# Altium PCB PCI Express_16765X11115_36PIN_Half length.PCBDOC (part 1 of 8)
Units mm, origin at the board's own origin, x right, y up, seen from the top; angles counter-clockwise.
Board outline 178 x 110.97 mm, 10 copper layers (Top Layer, Int1 (GND), Int2 (Sign), Int3 (Sign), Int4 (PWR), Int5 (GND), Int6 (Sign), Int7 (Sign), Int8 (GND), Bottom Layer), stack 1.429 mm thick; 528 components, 525 nets, 2272 pads, 1491 vias.
Unrouted connection lines stored in the file: 373.
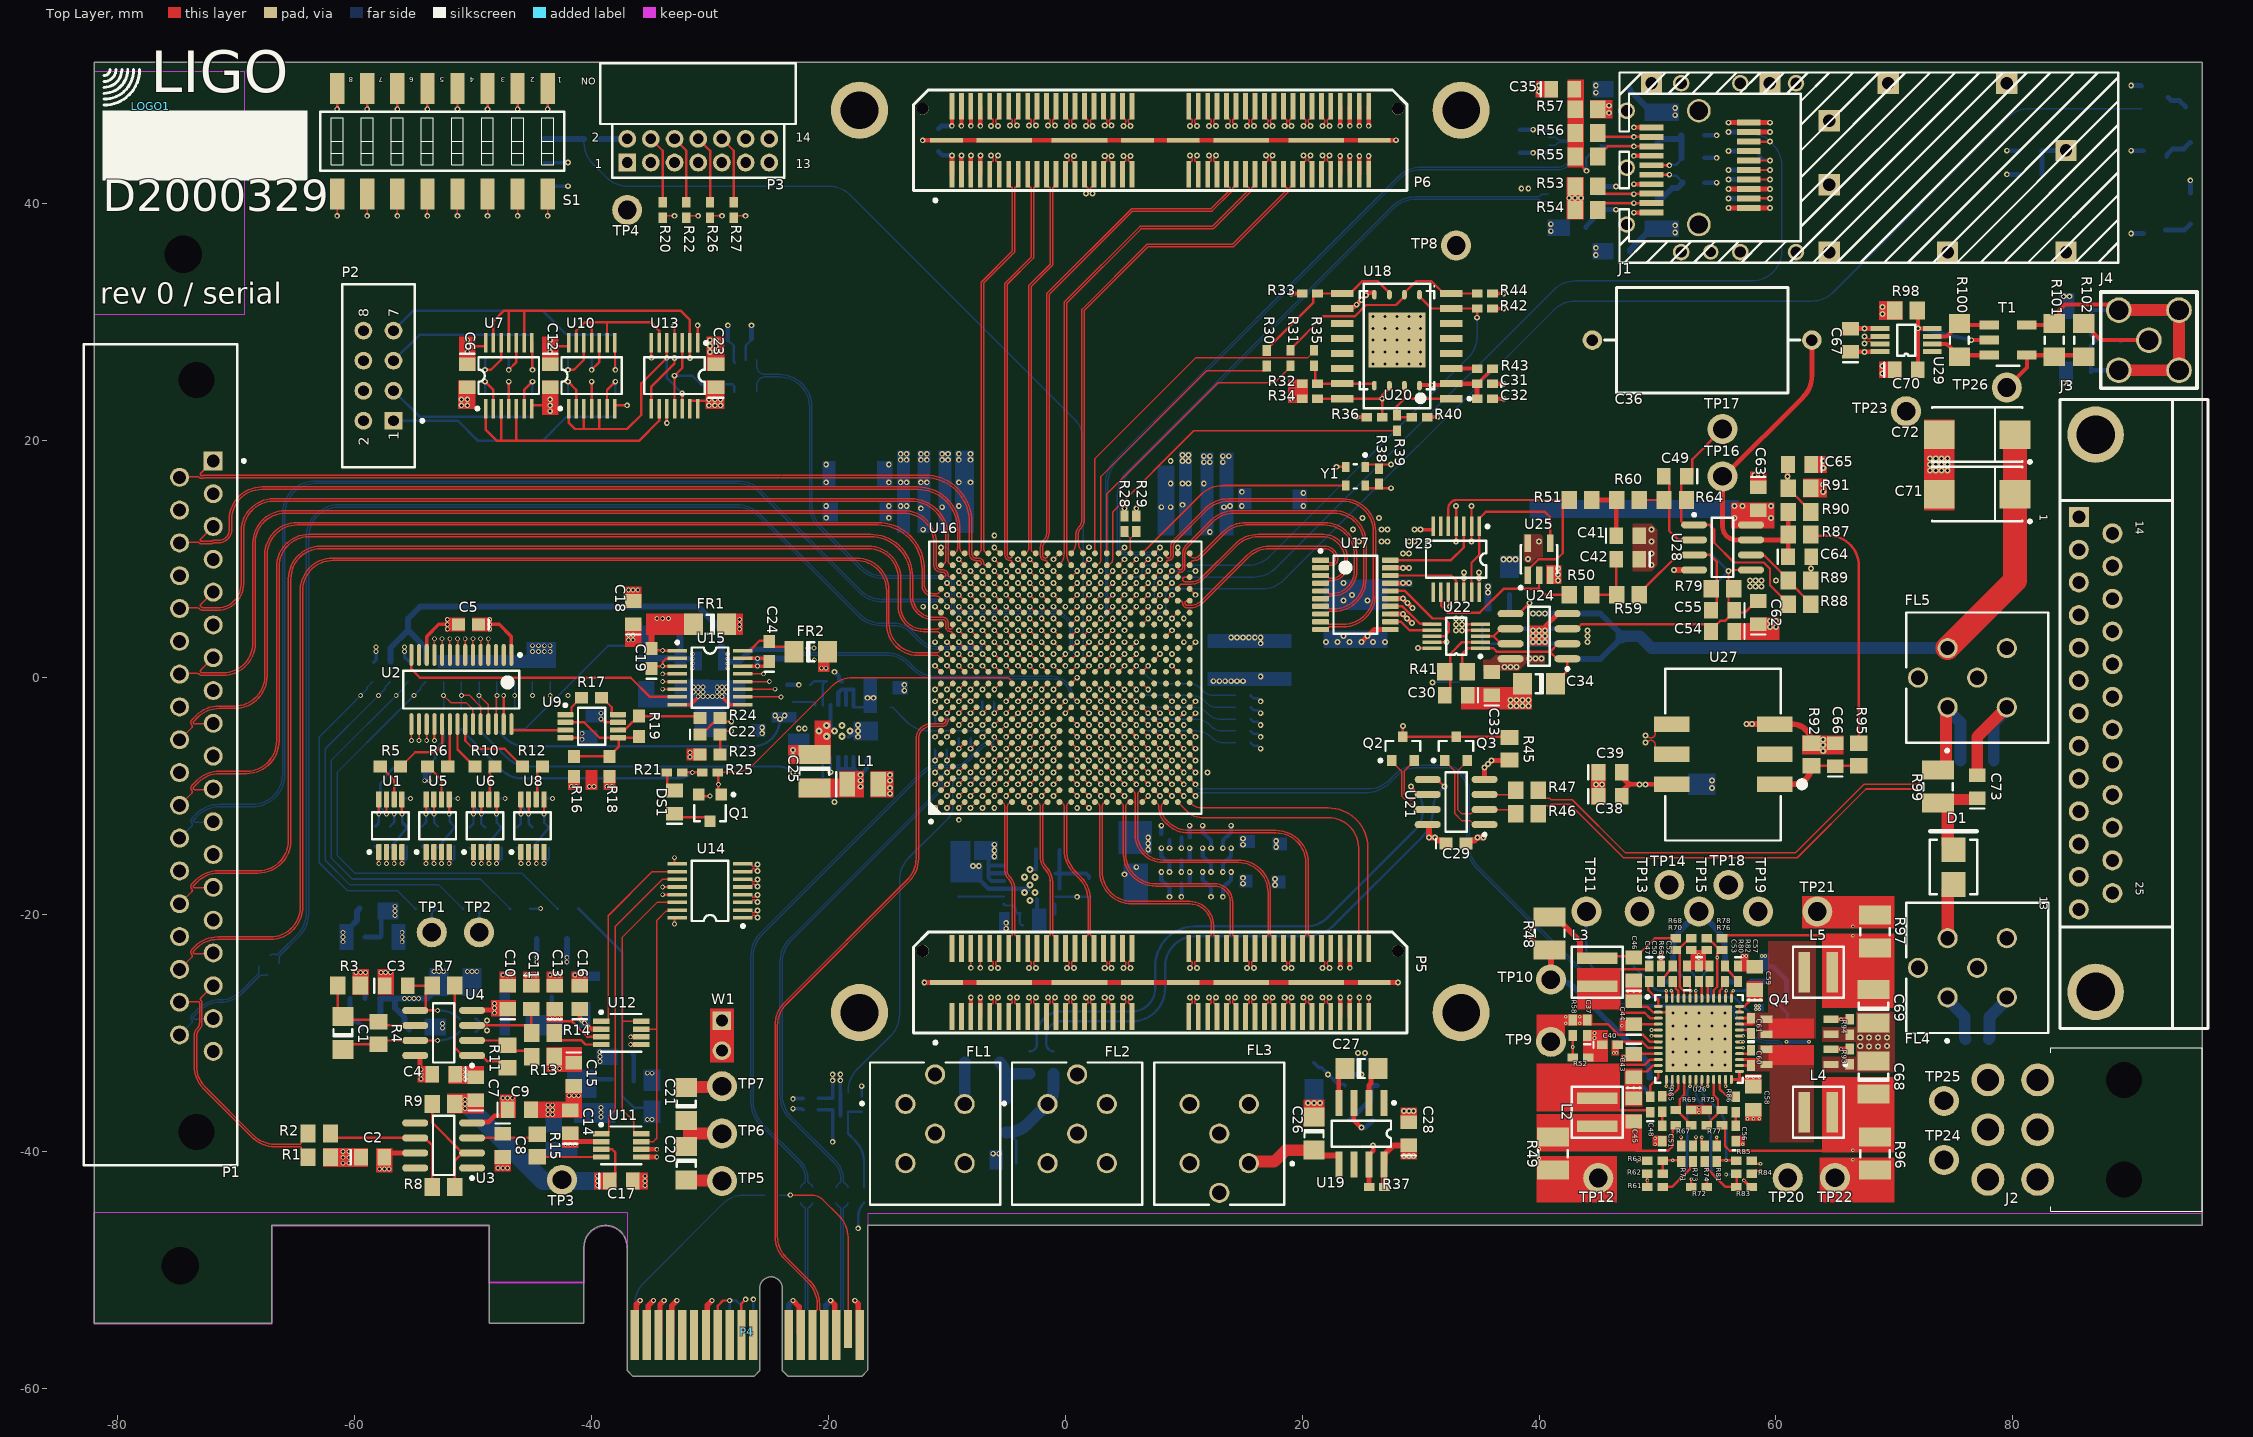
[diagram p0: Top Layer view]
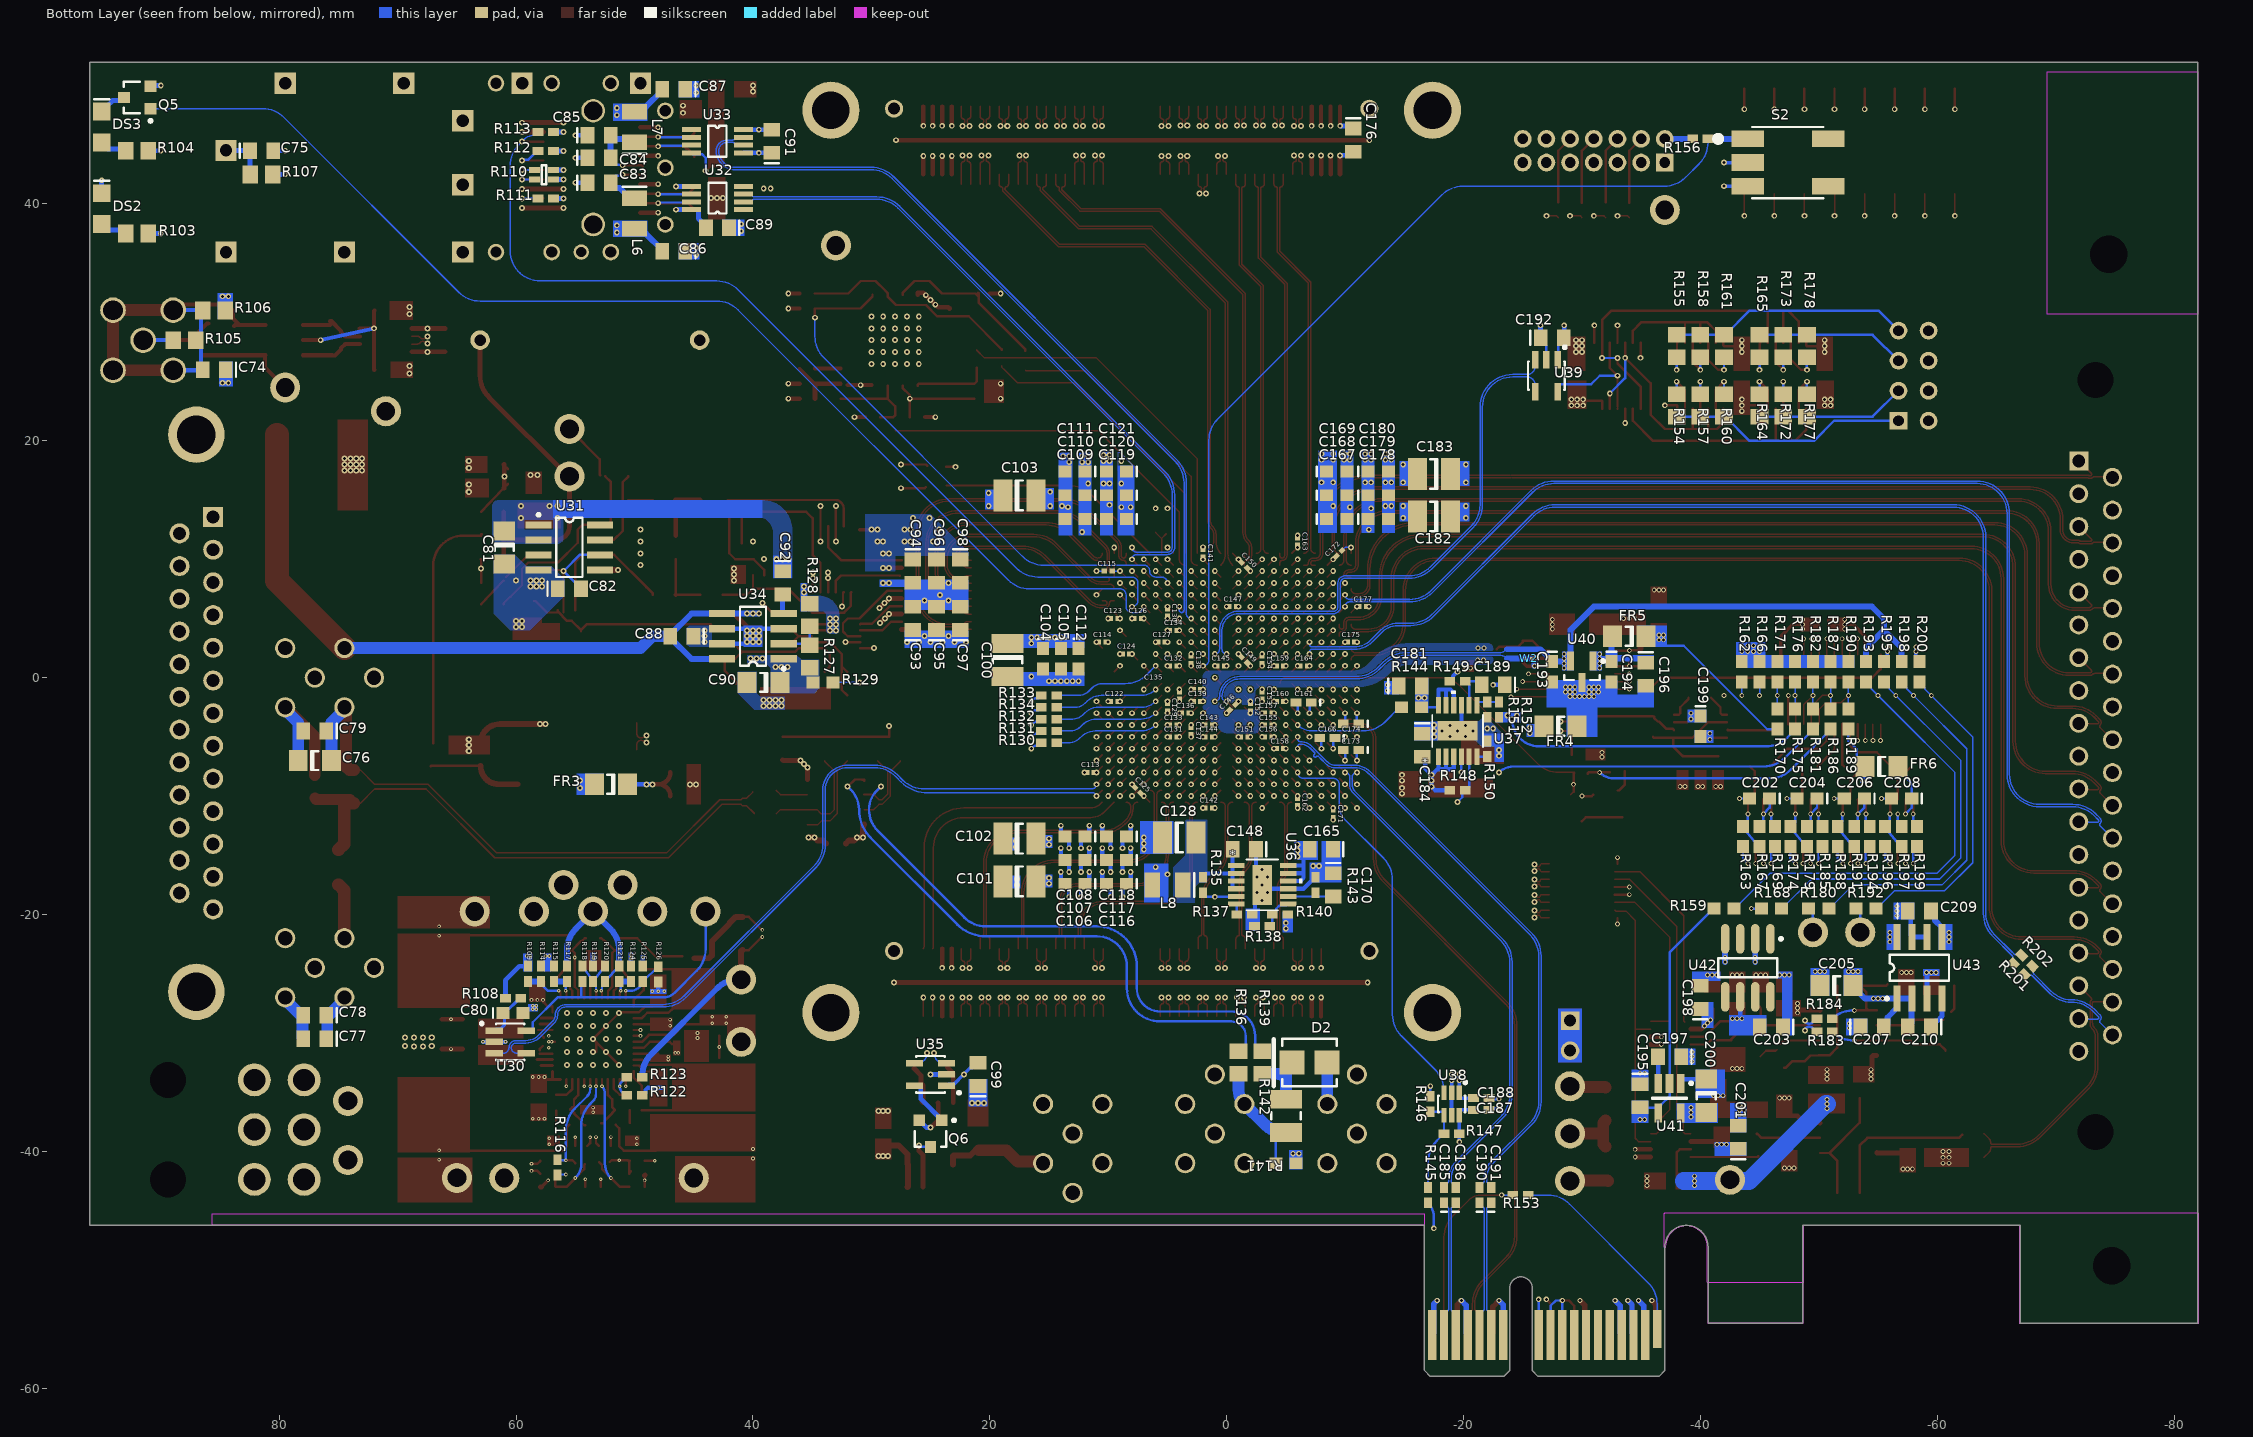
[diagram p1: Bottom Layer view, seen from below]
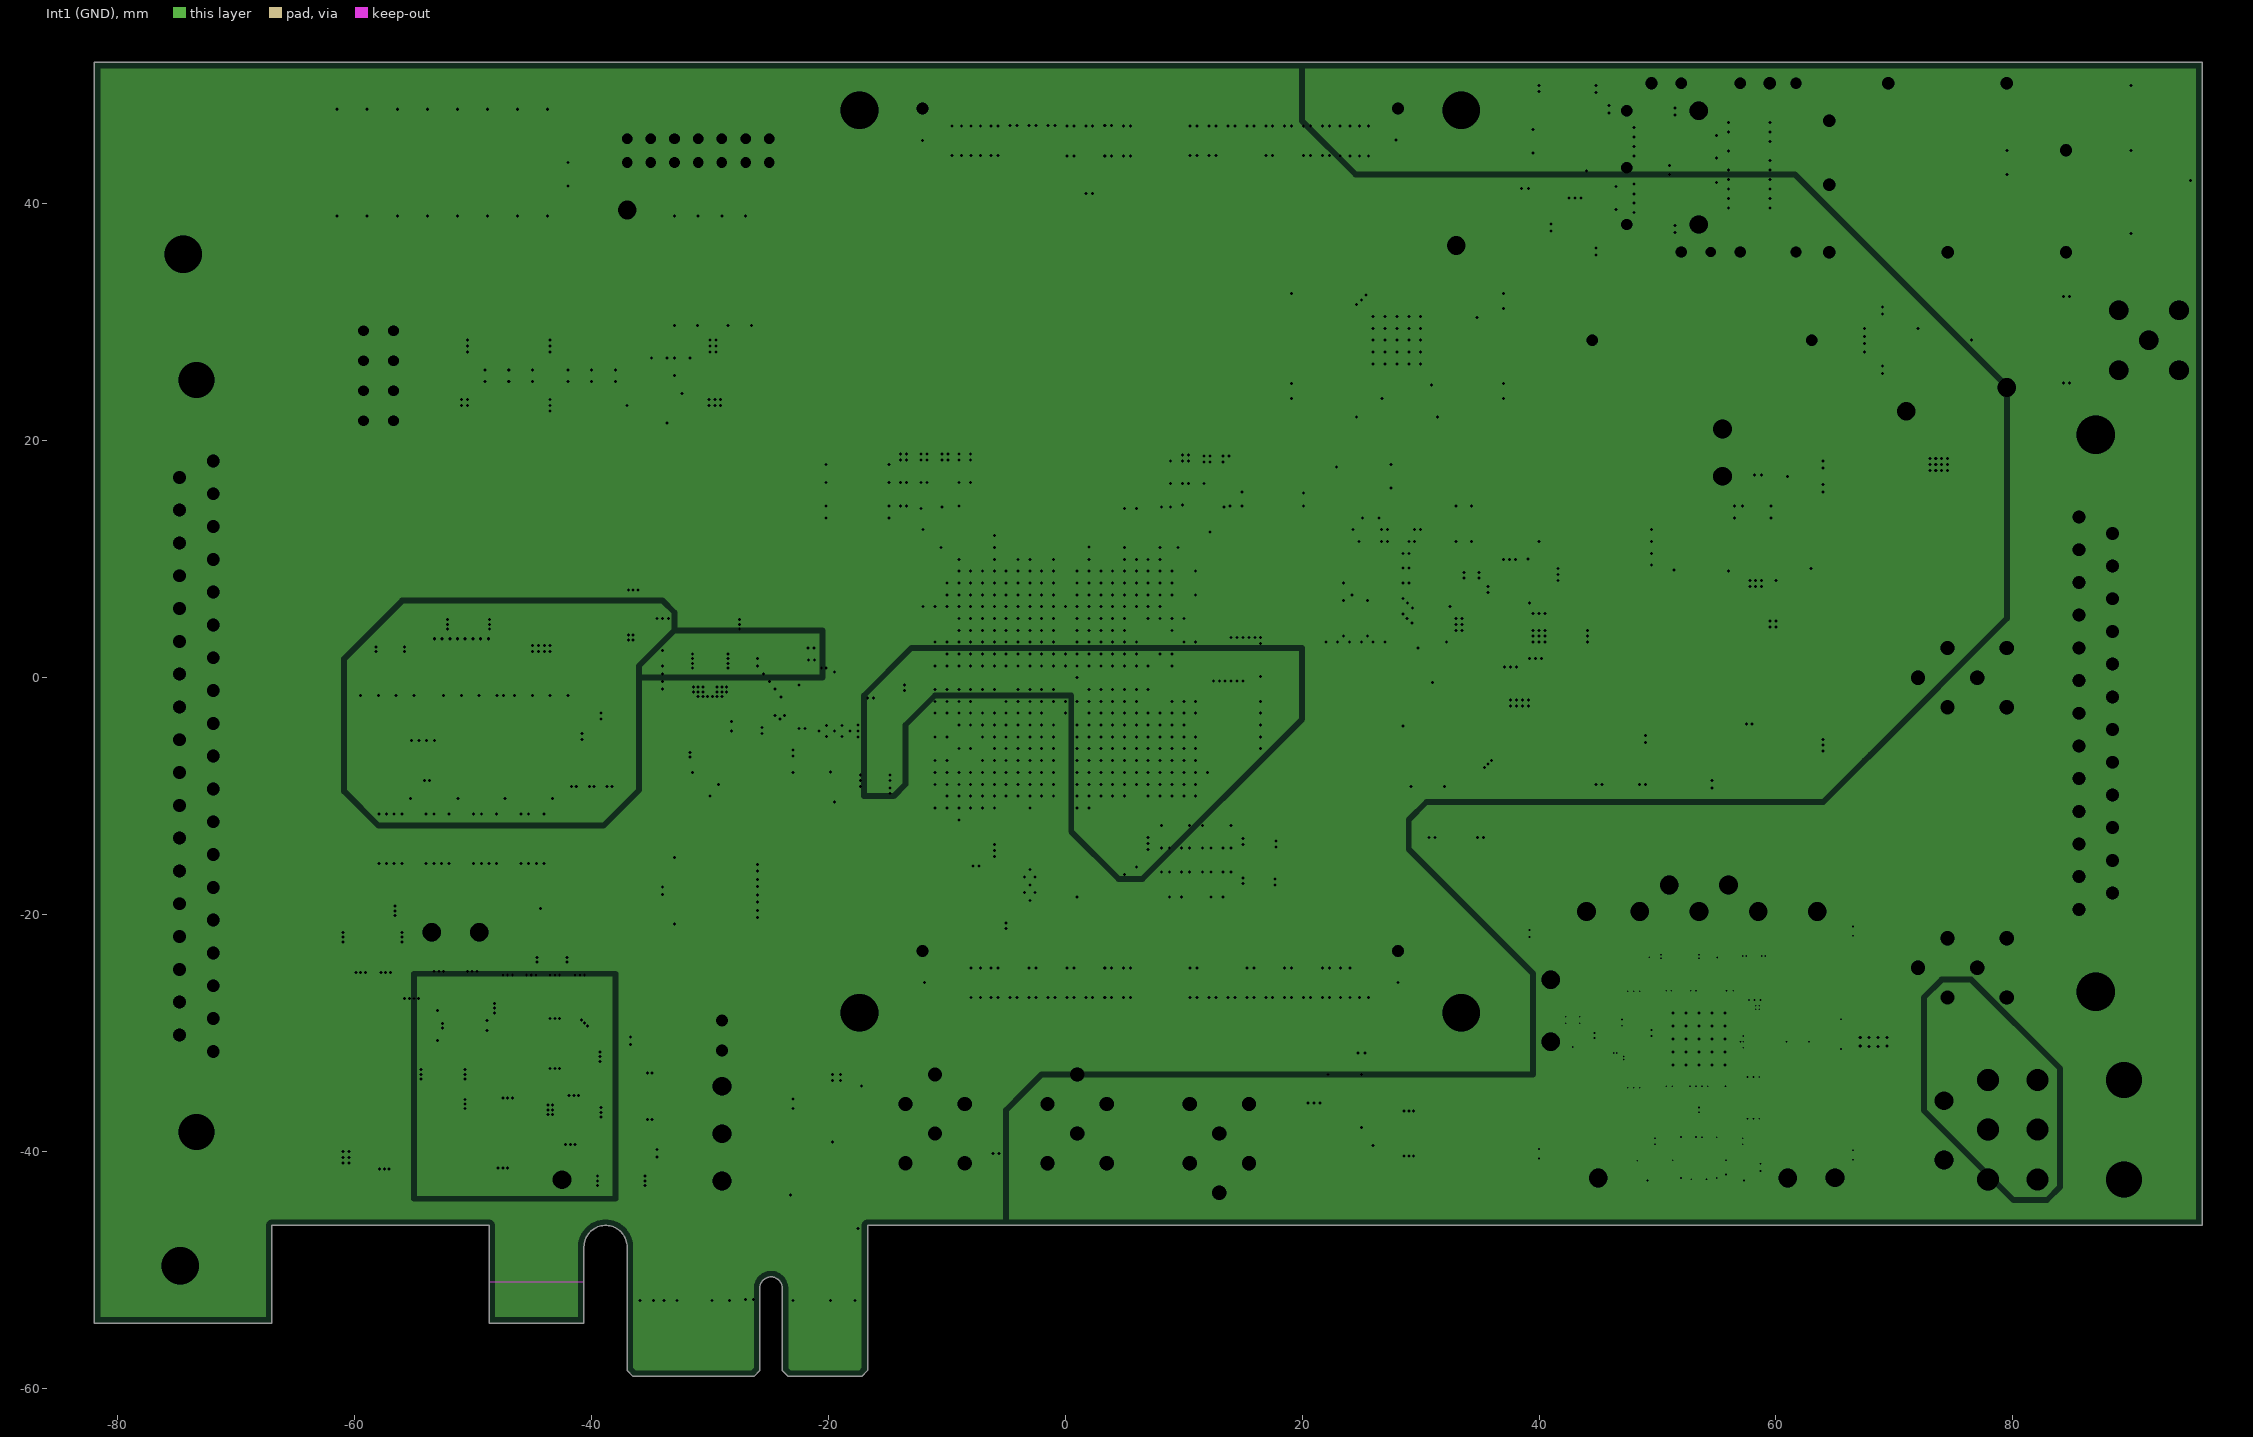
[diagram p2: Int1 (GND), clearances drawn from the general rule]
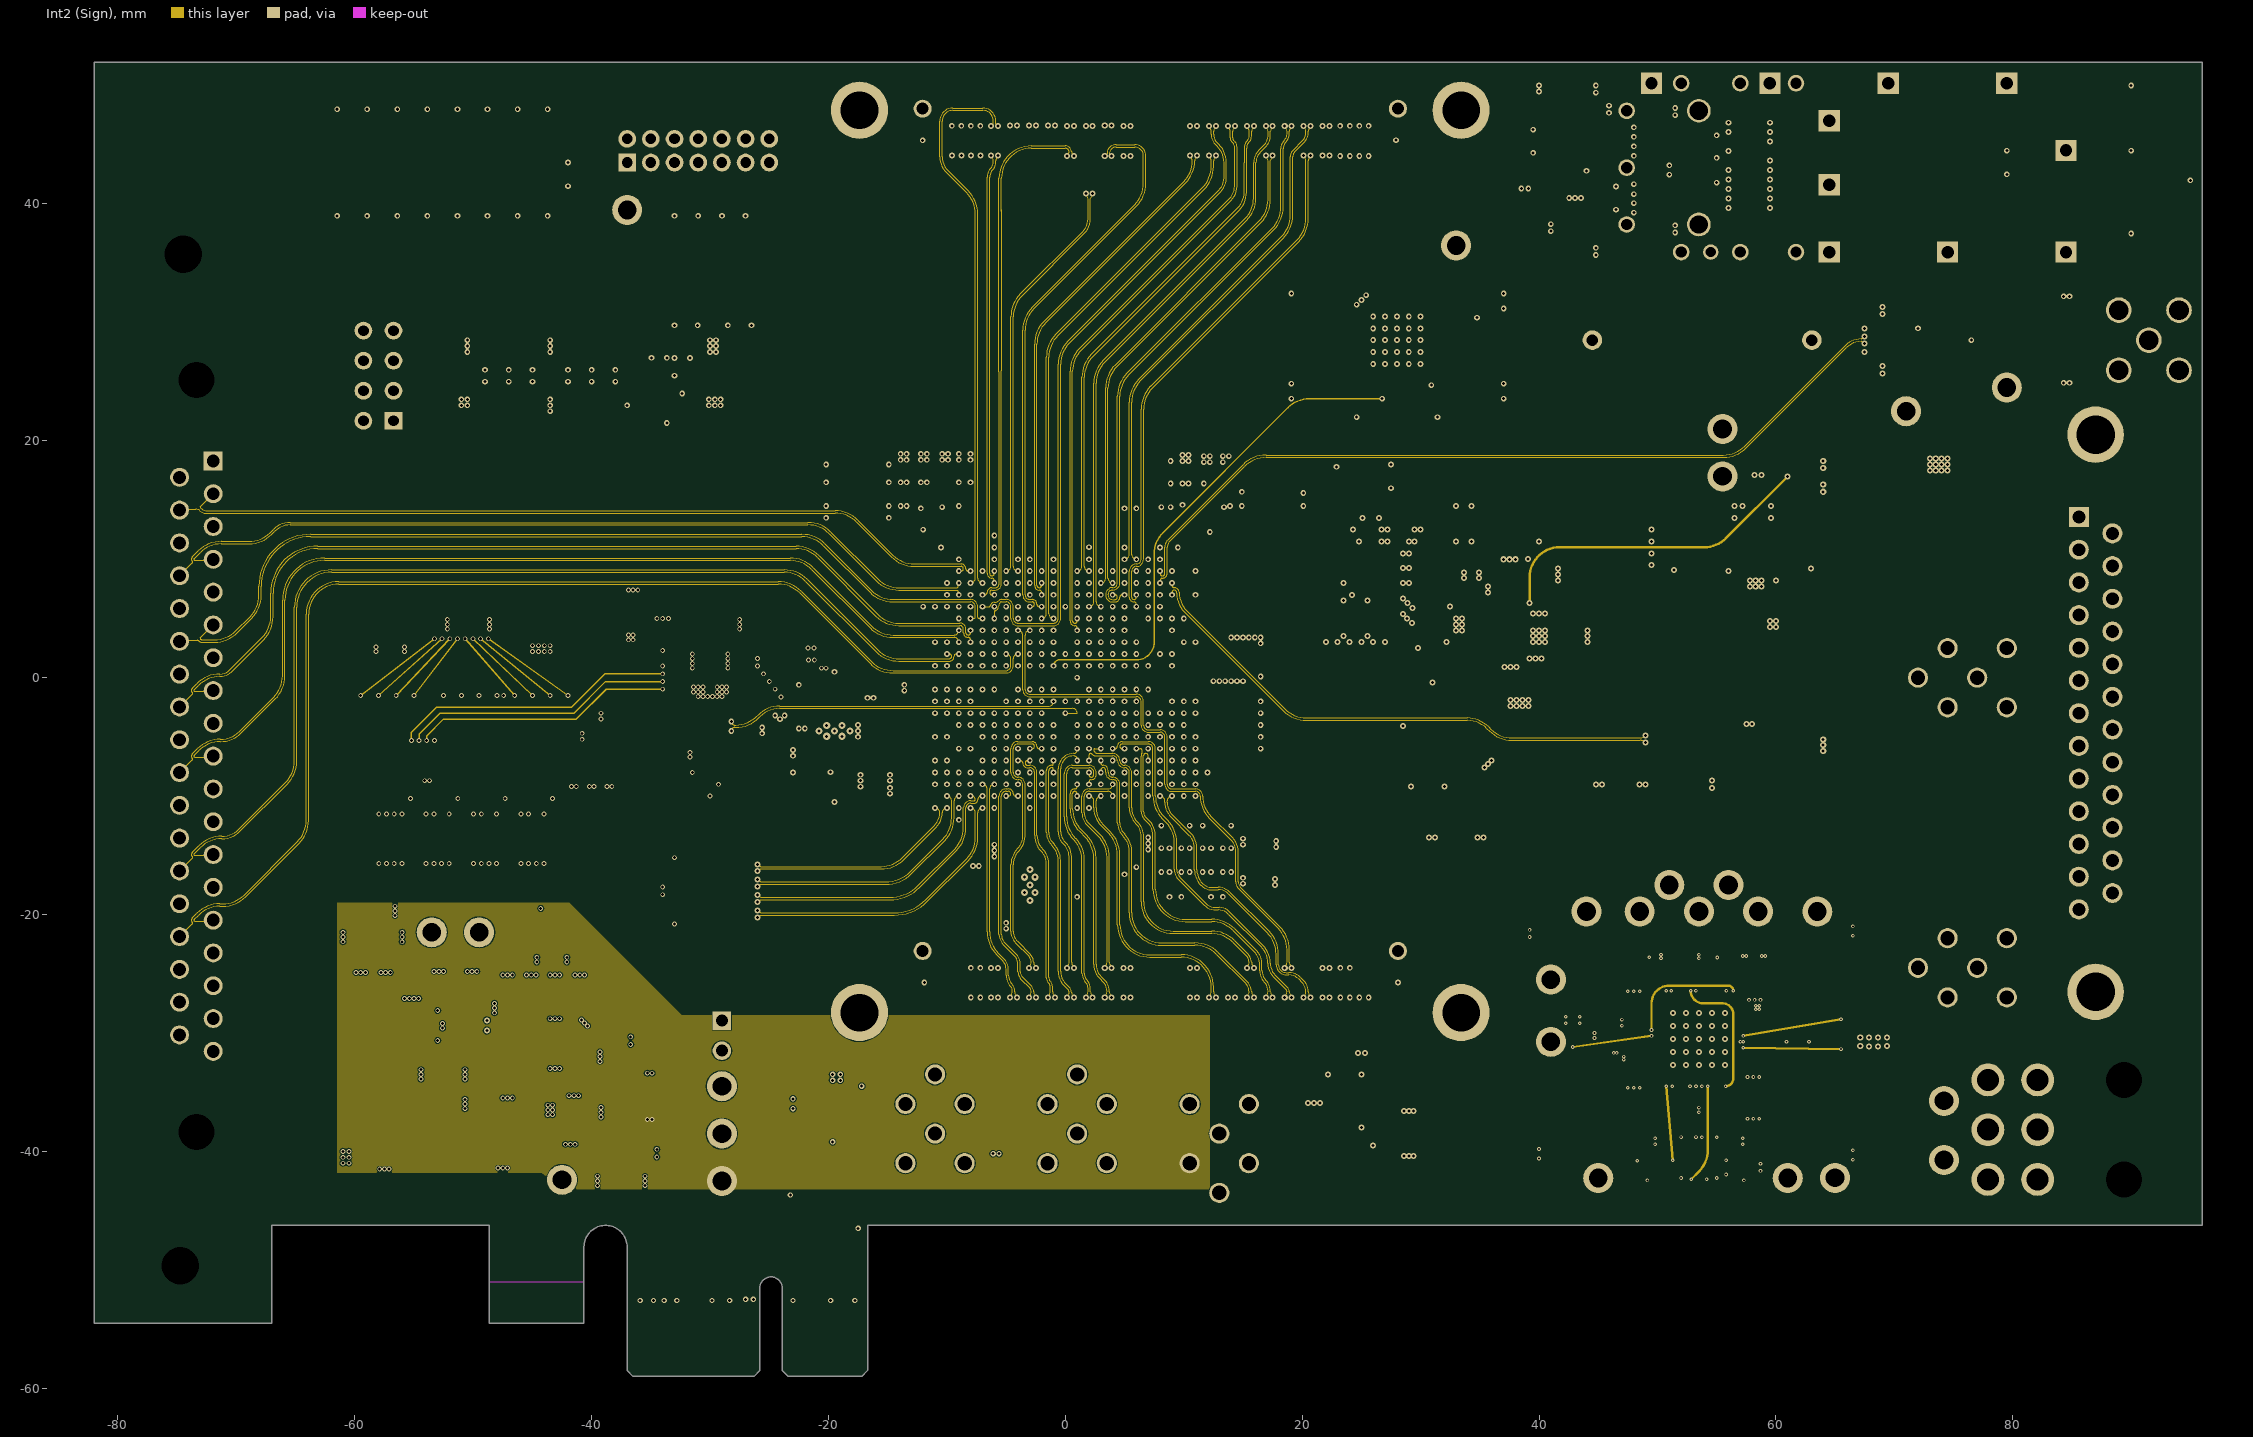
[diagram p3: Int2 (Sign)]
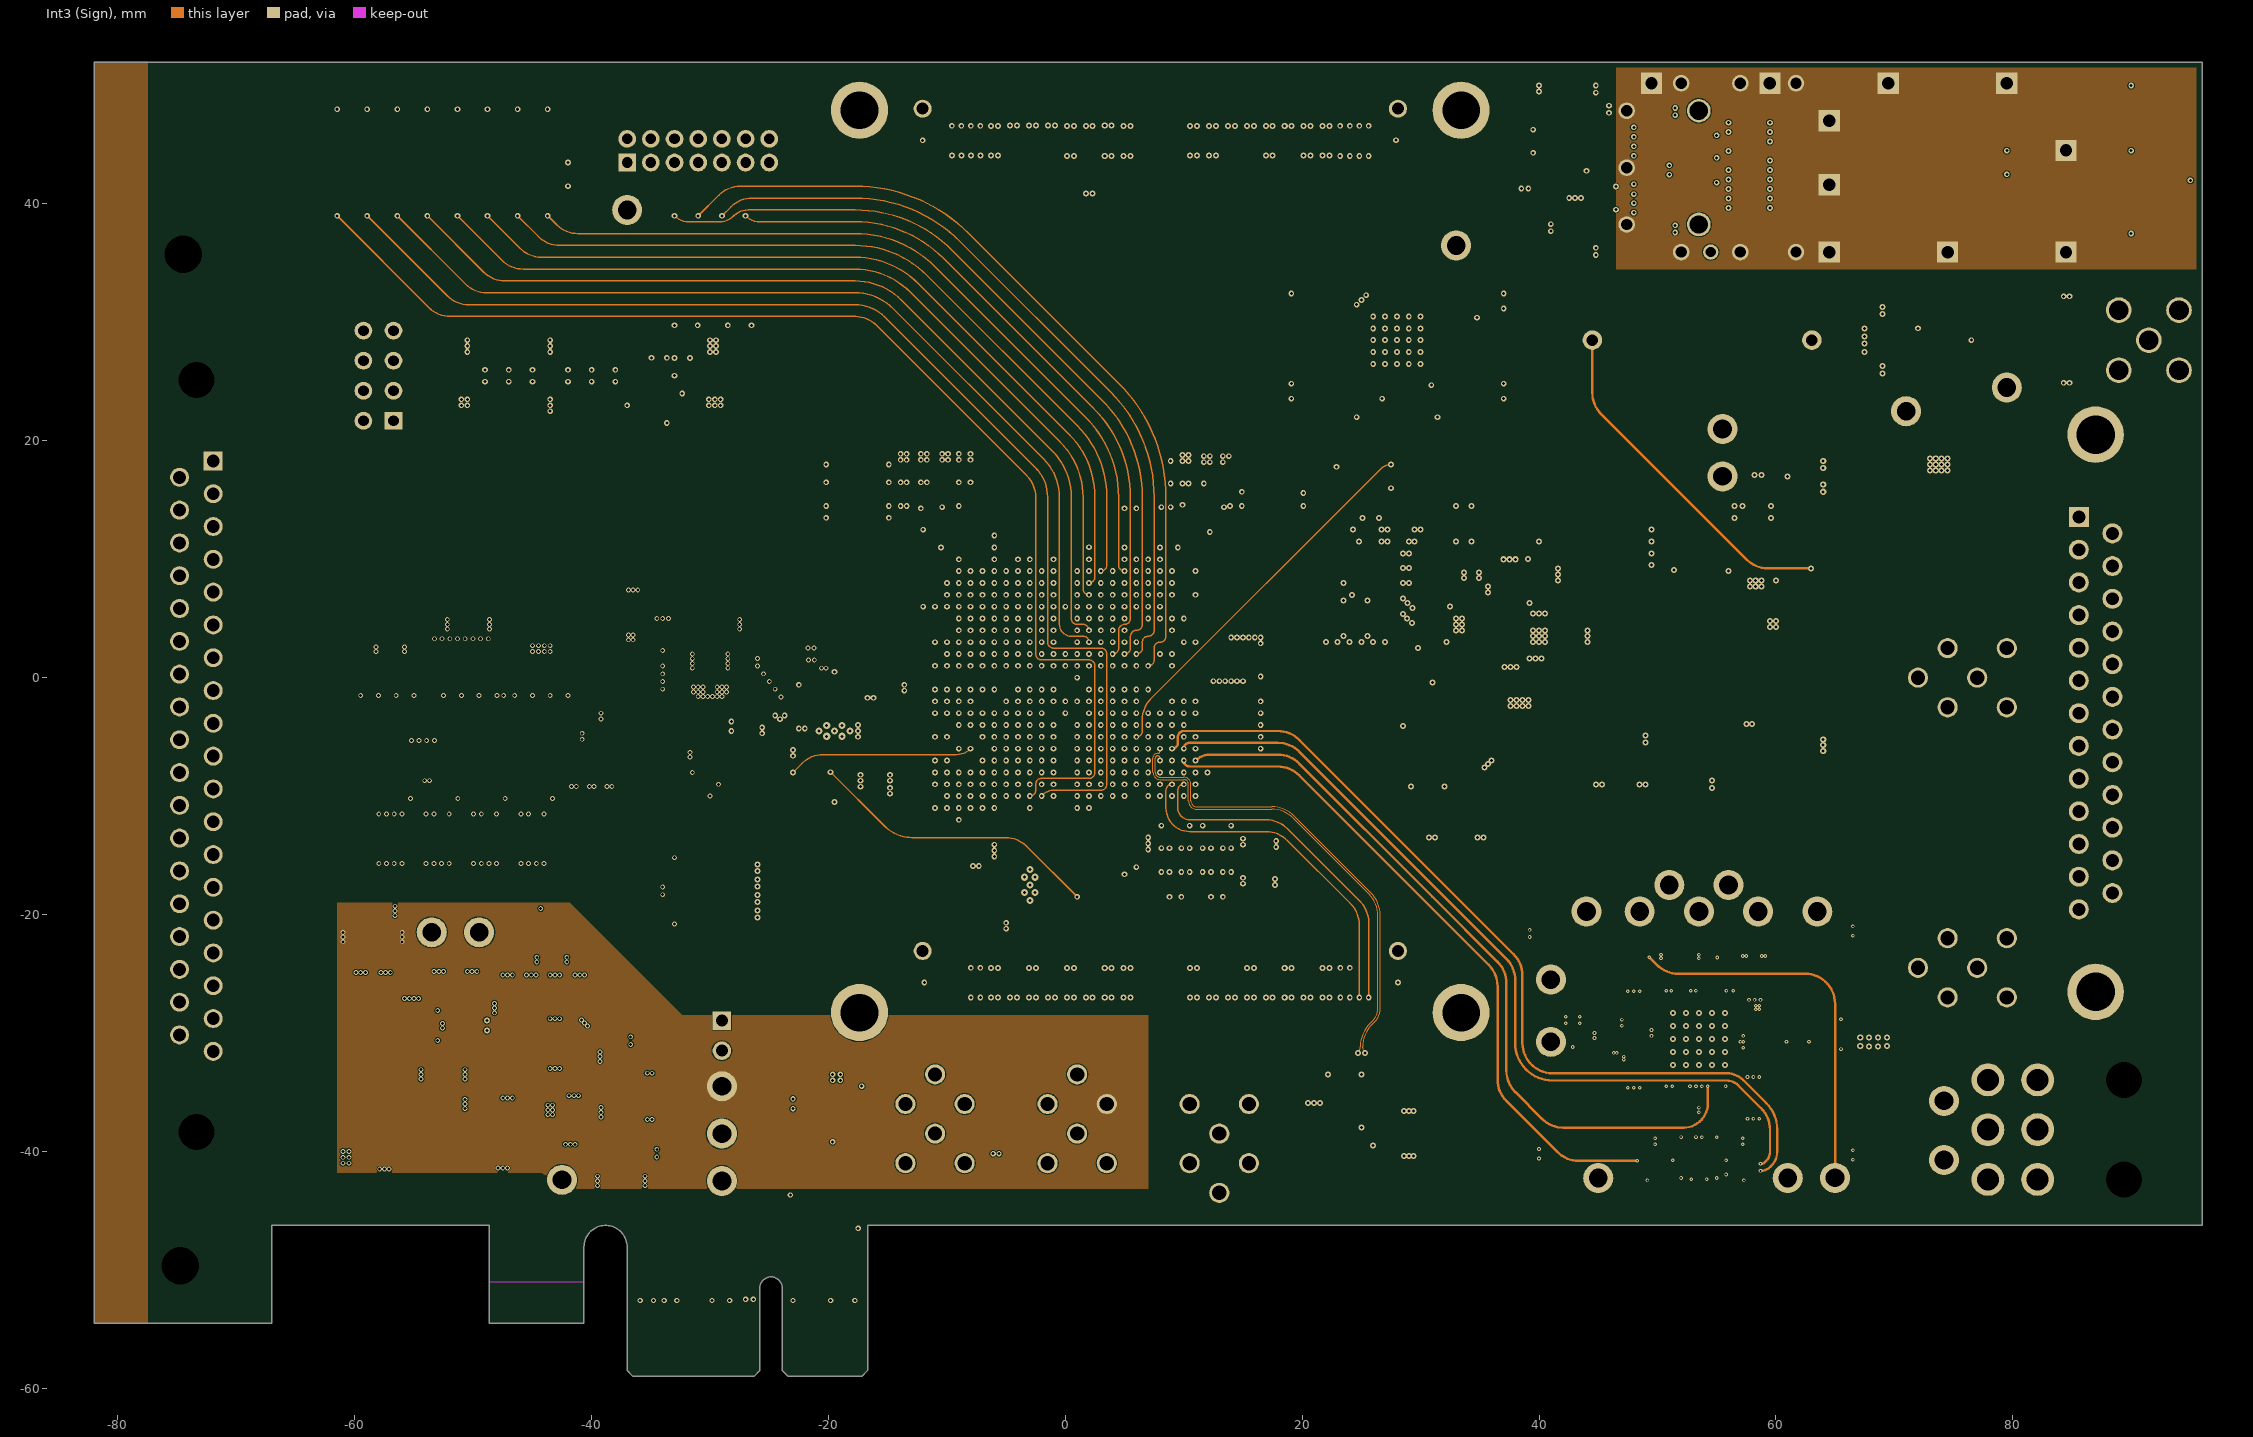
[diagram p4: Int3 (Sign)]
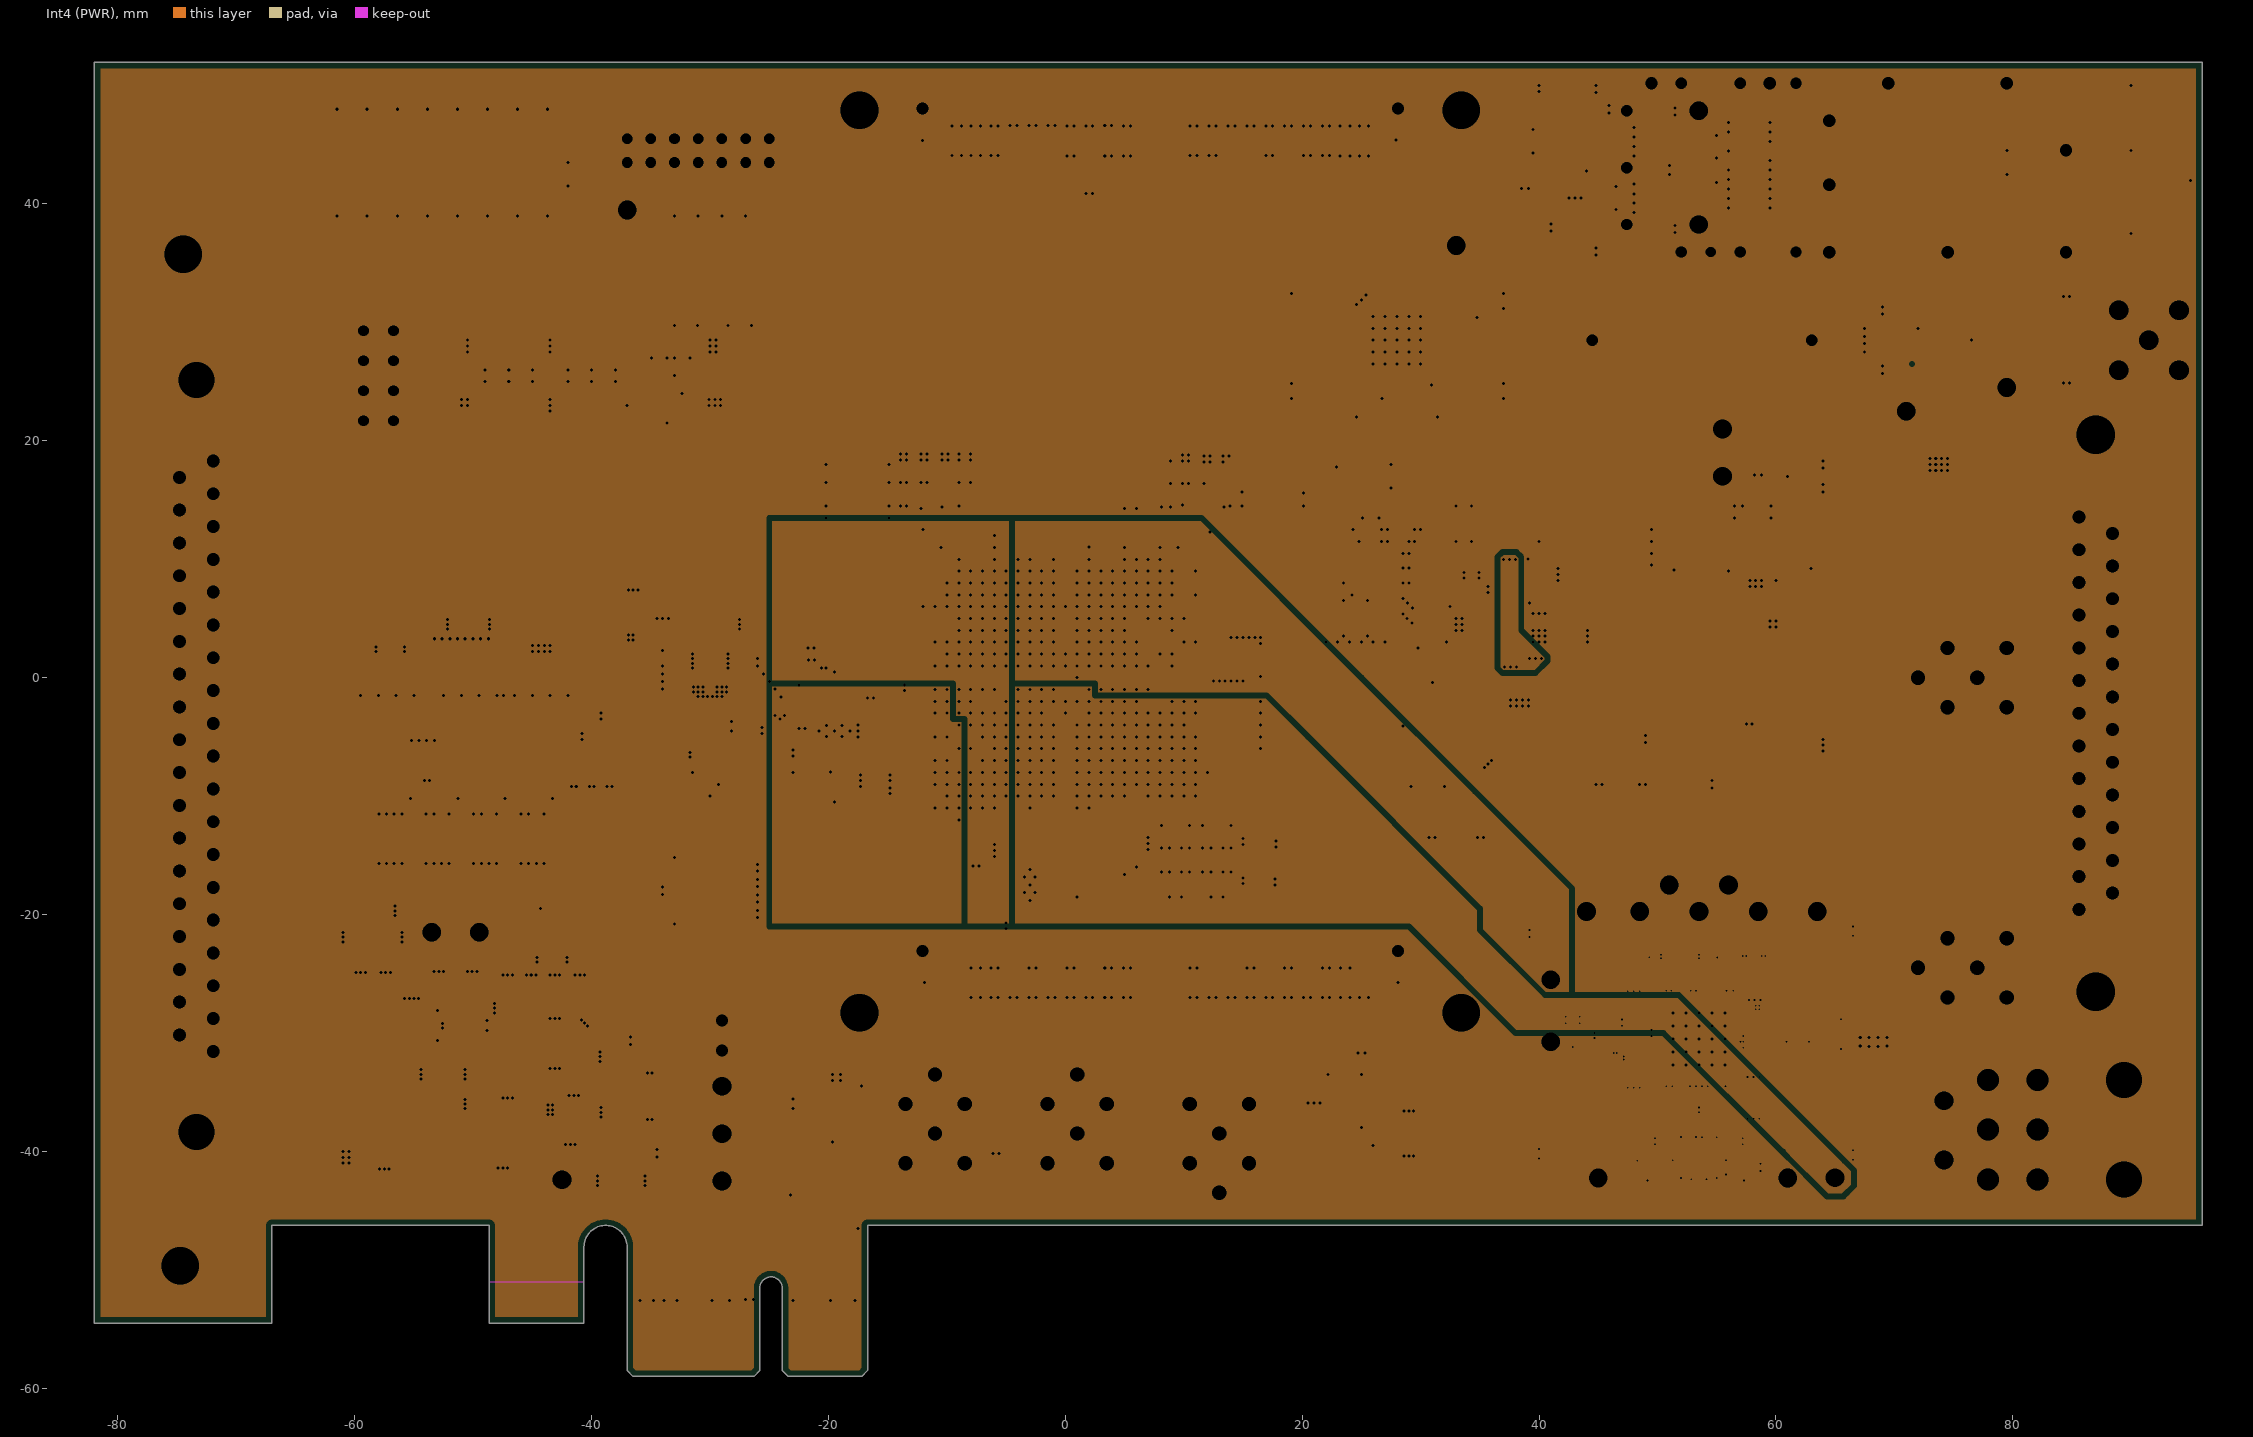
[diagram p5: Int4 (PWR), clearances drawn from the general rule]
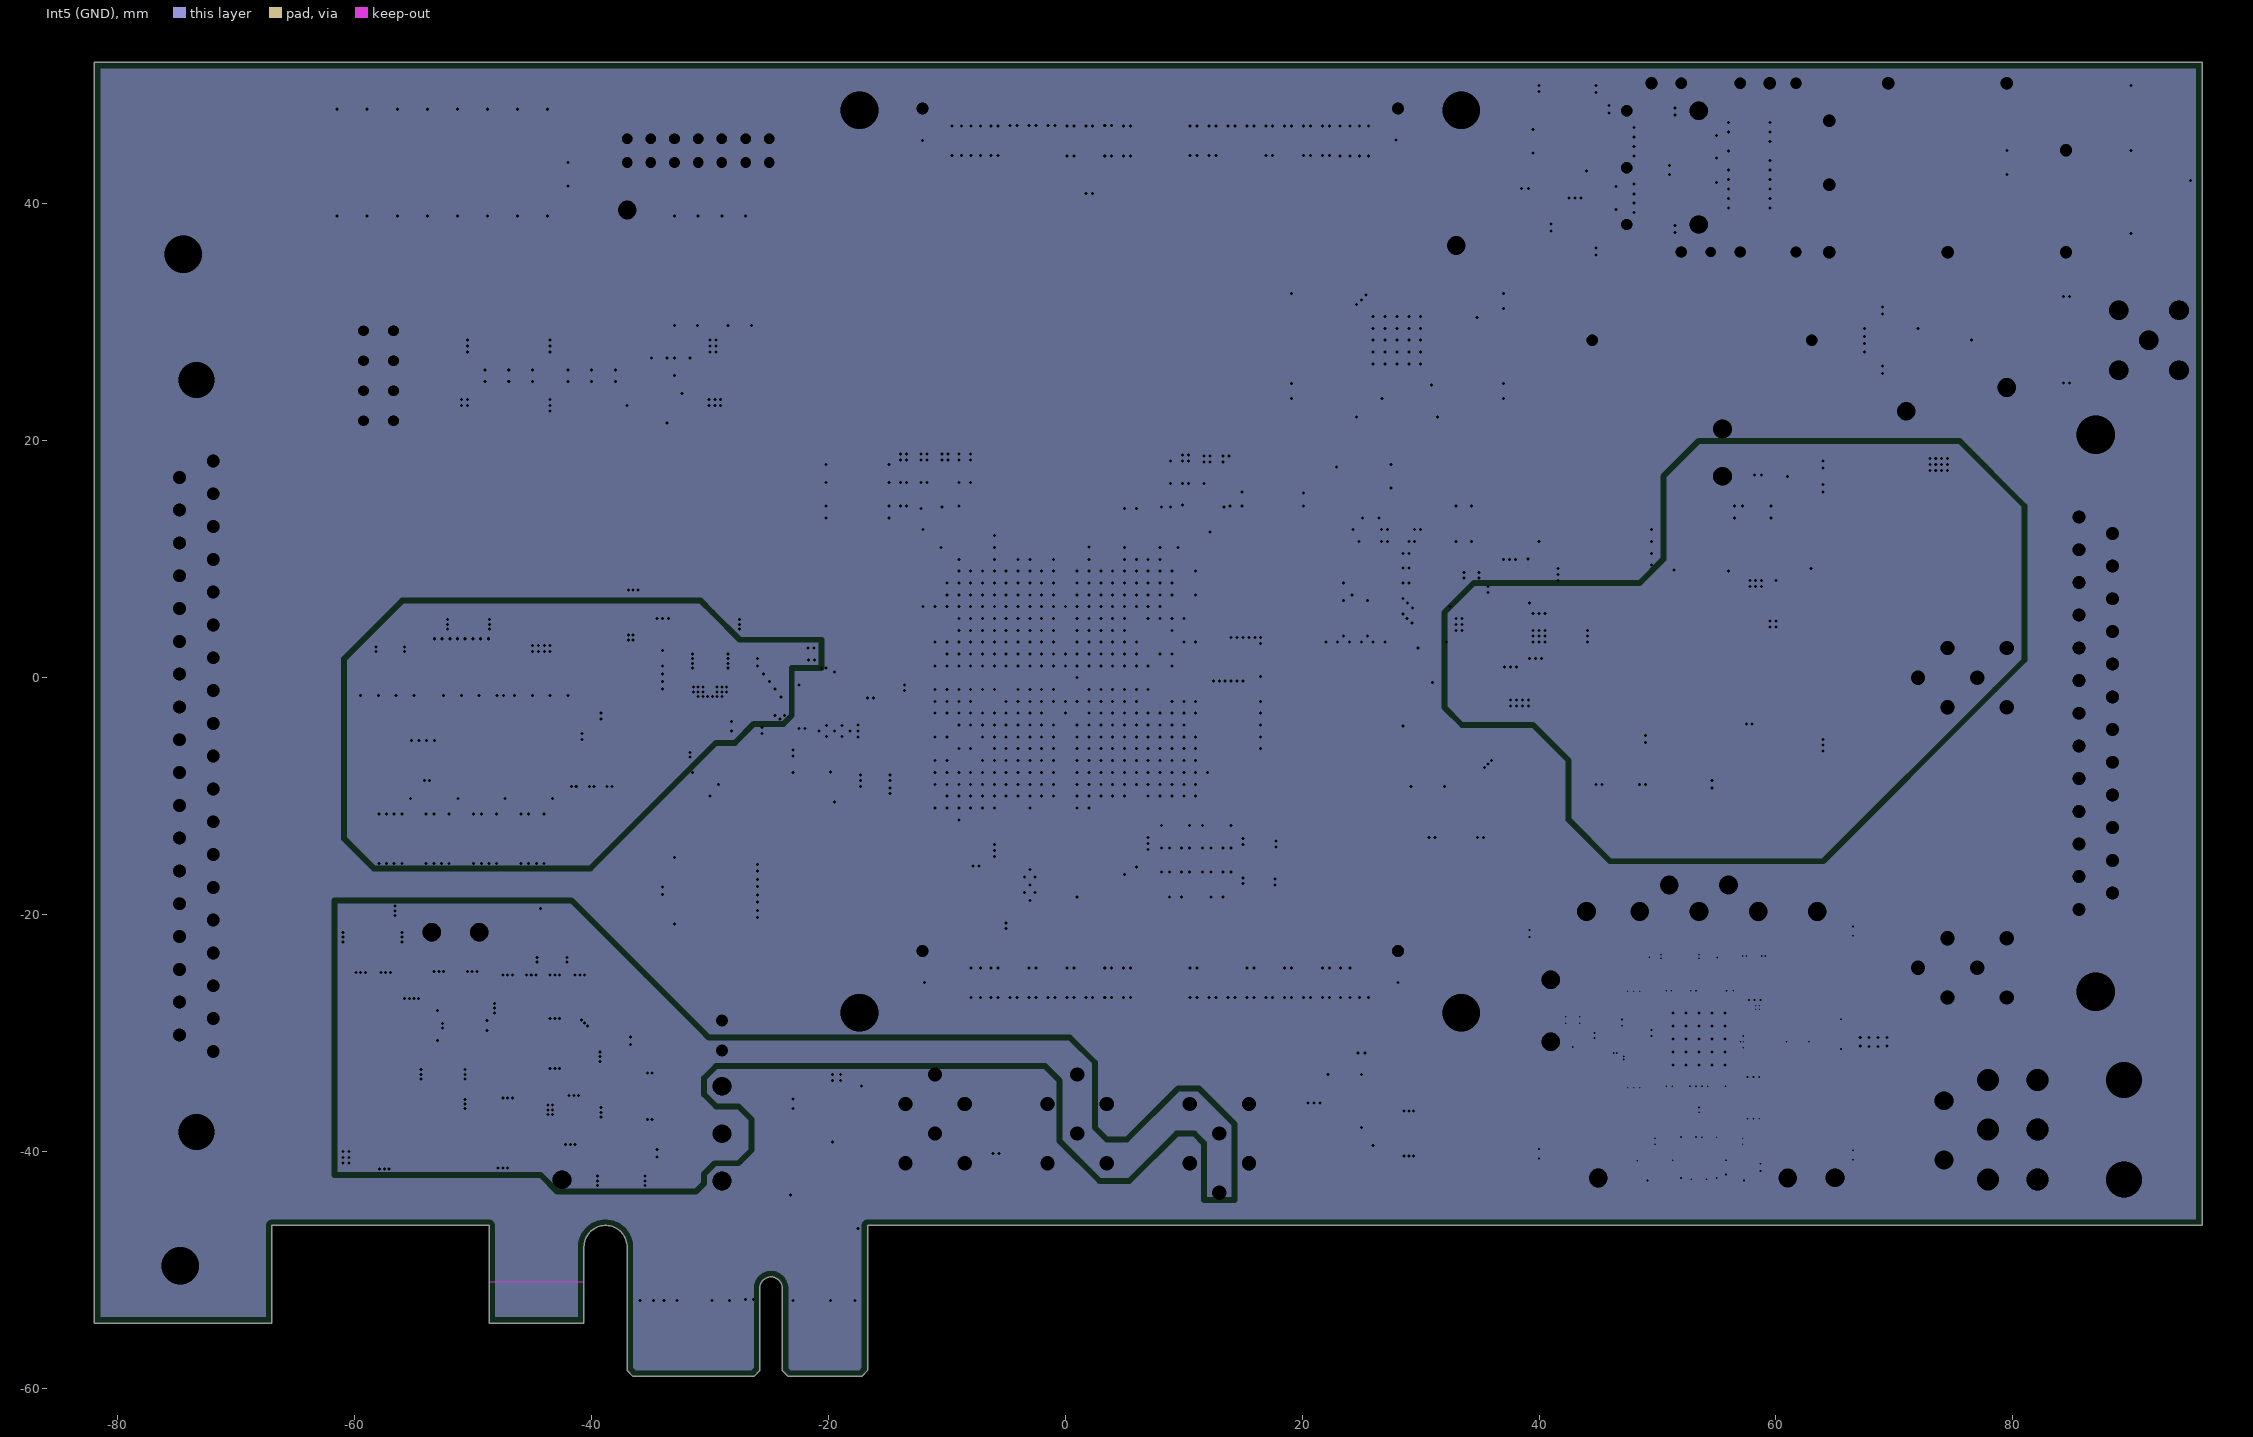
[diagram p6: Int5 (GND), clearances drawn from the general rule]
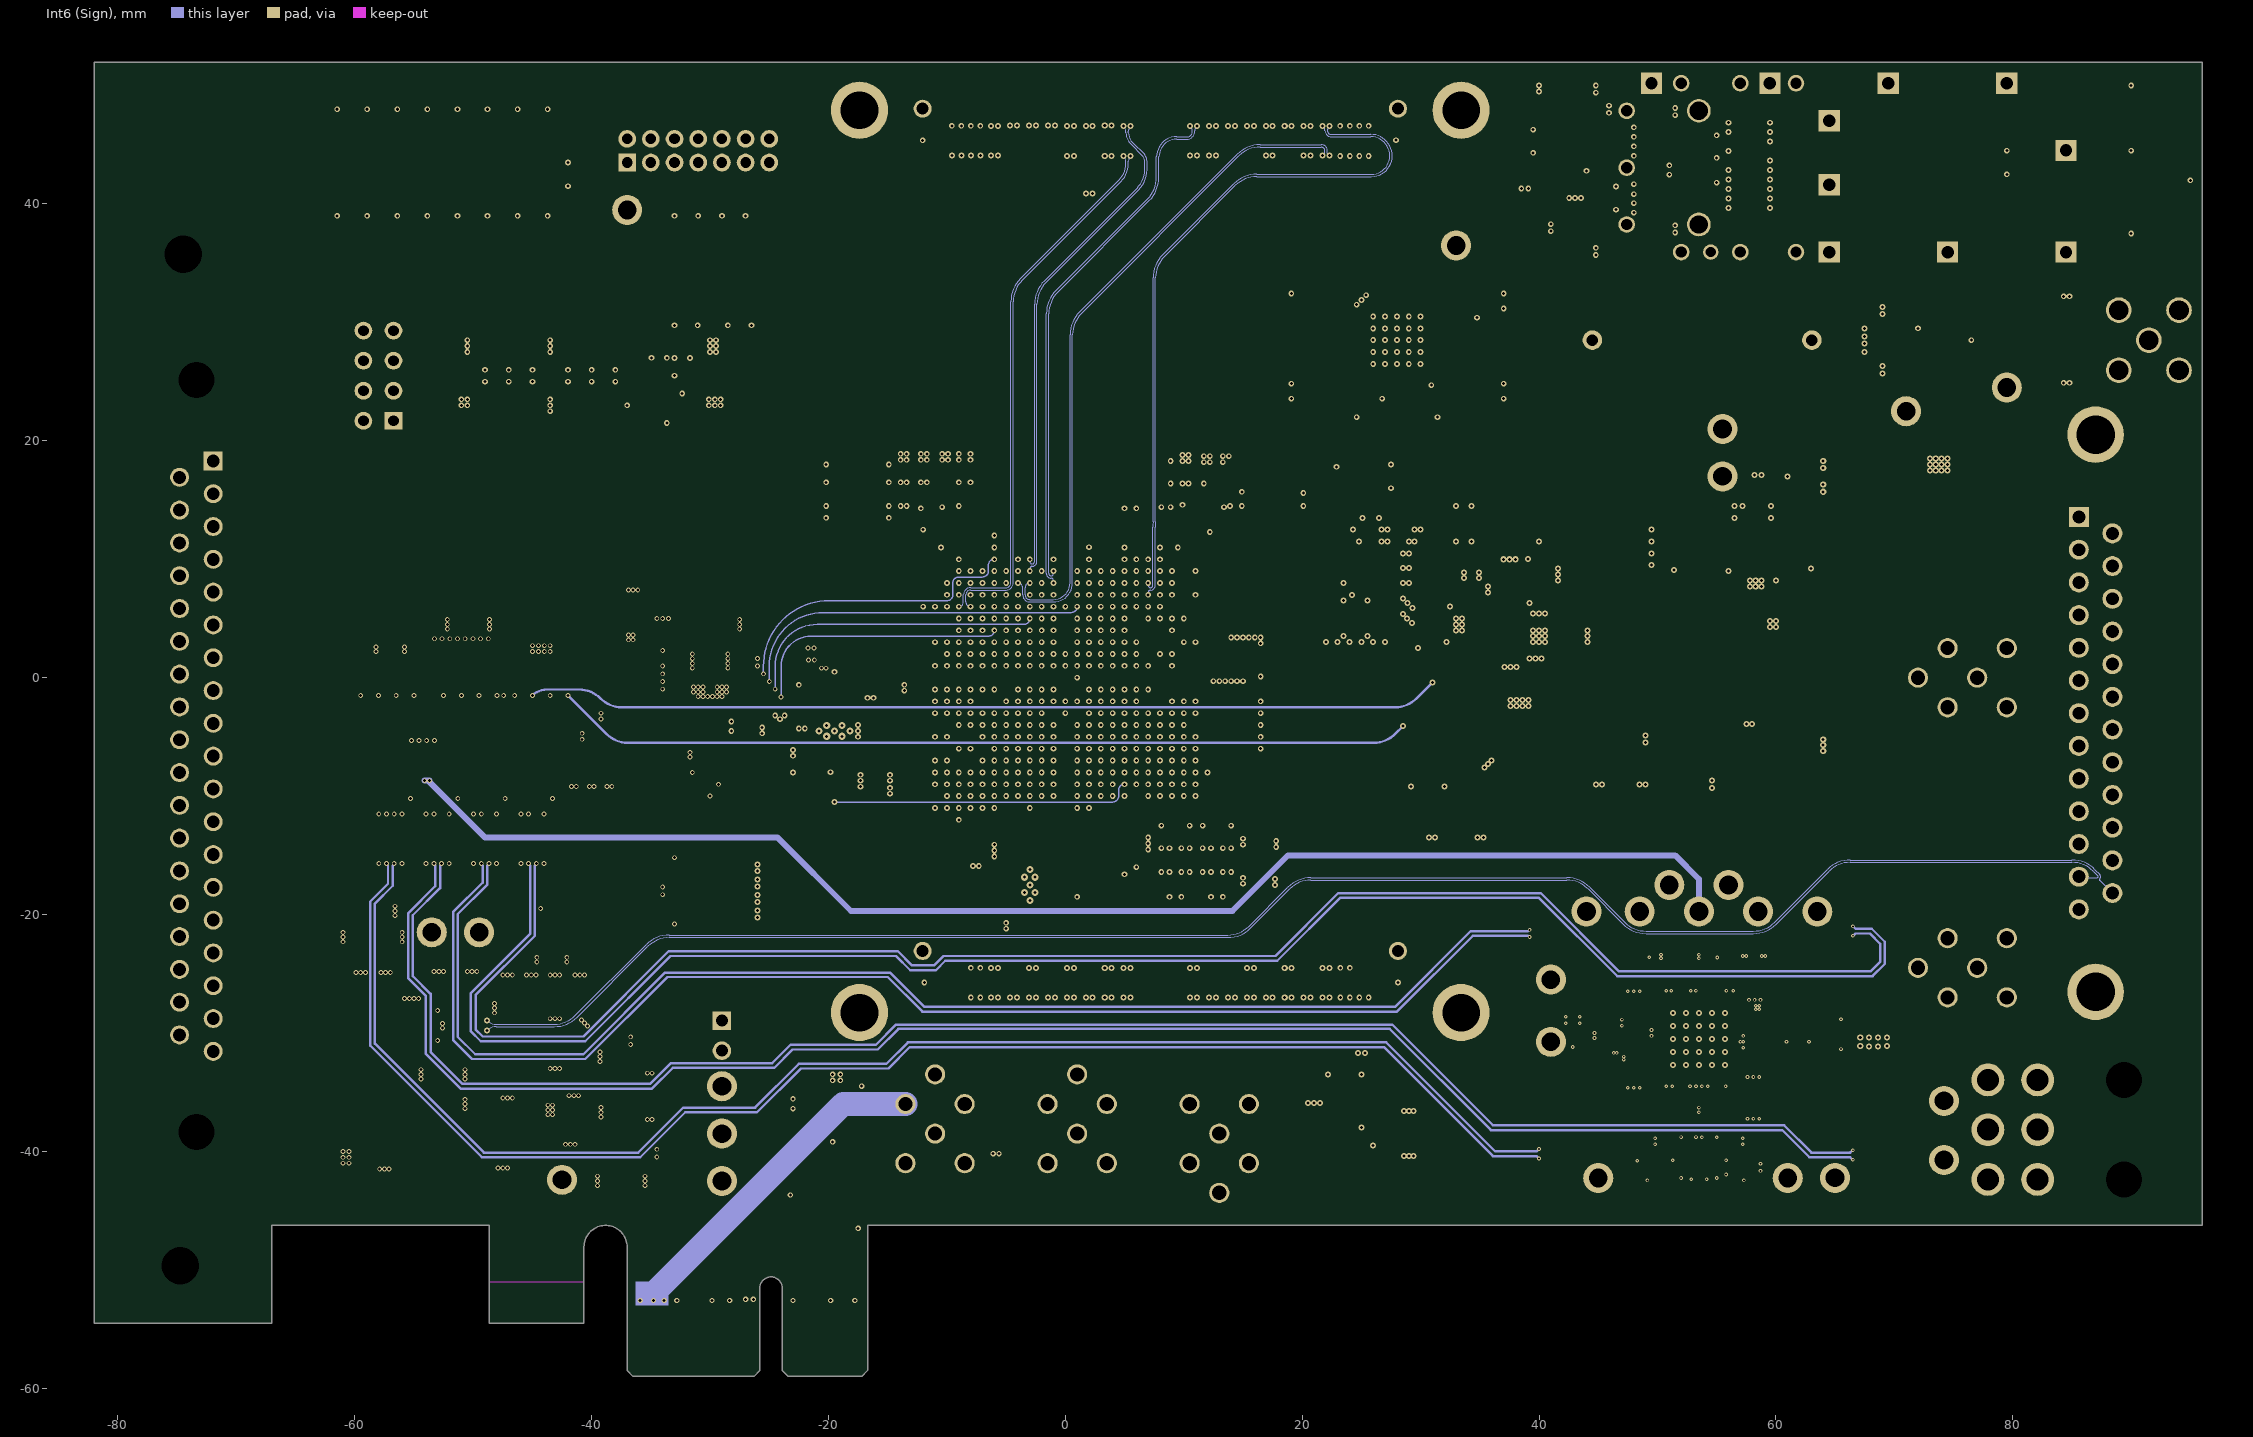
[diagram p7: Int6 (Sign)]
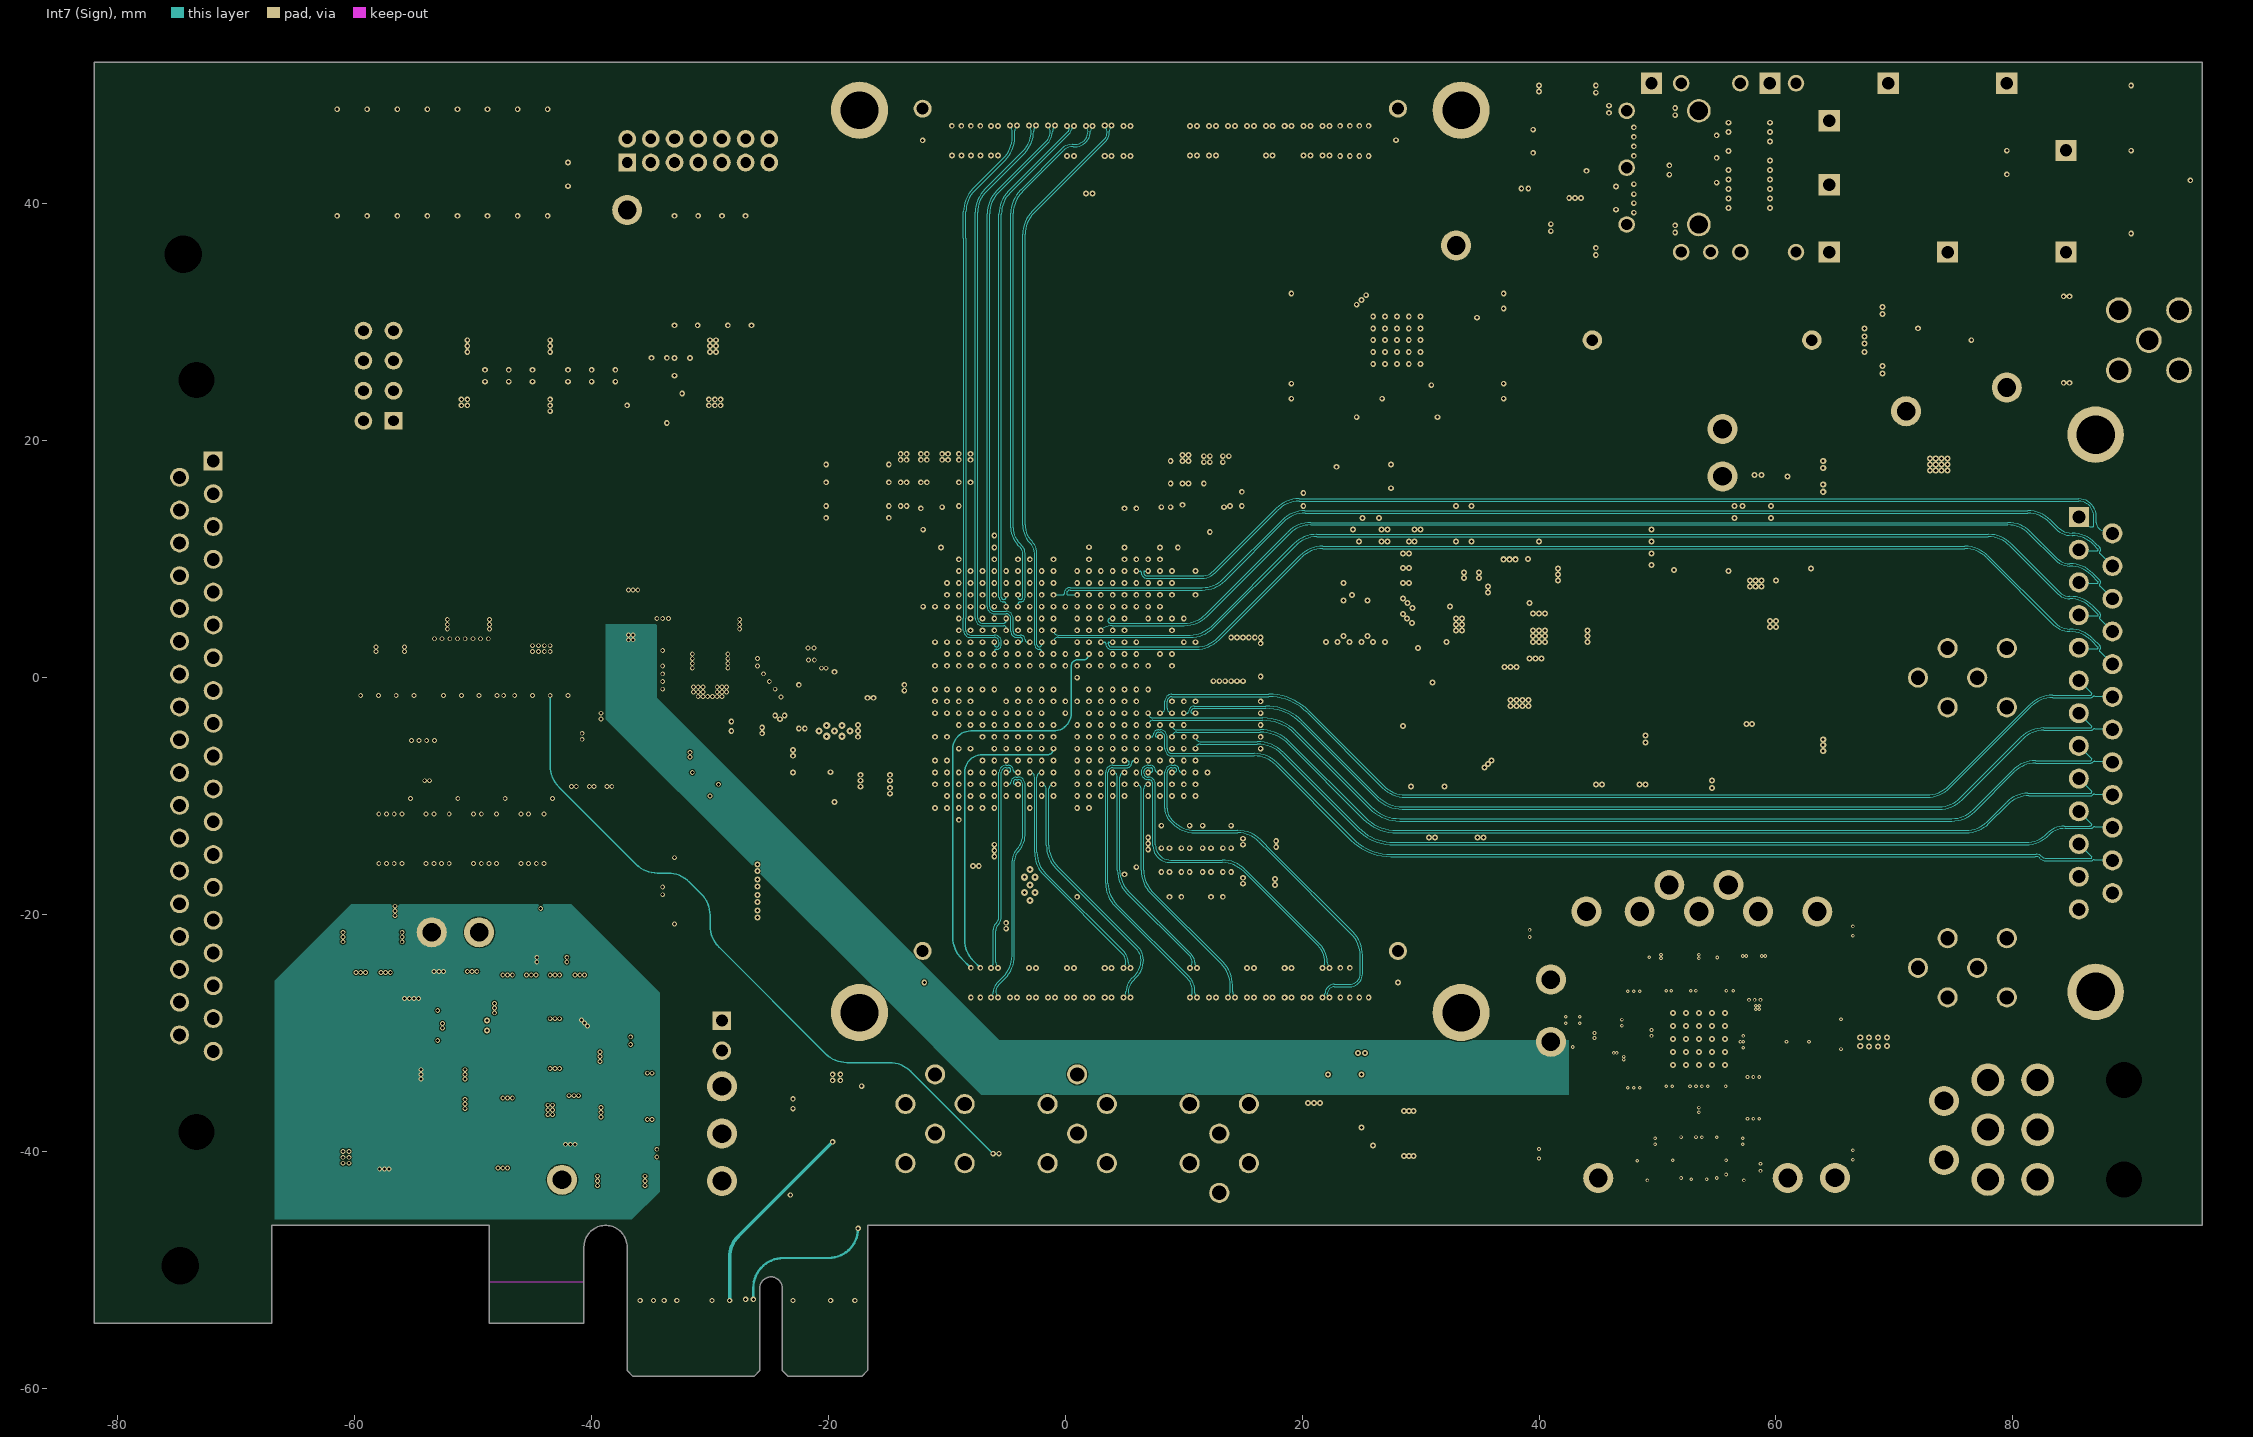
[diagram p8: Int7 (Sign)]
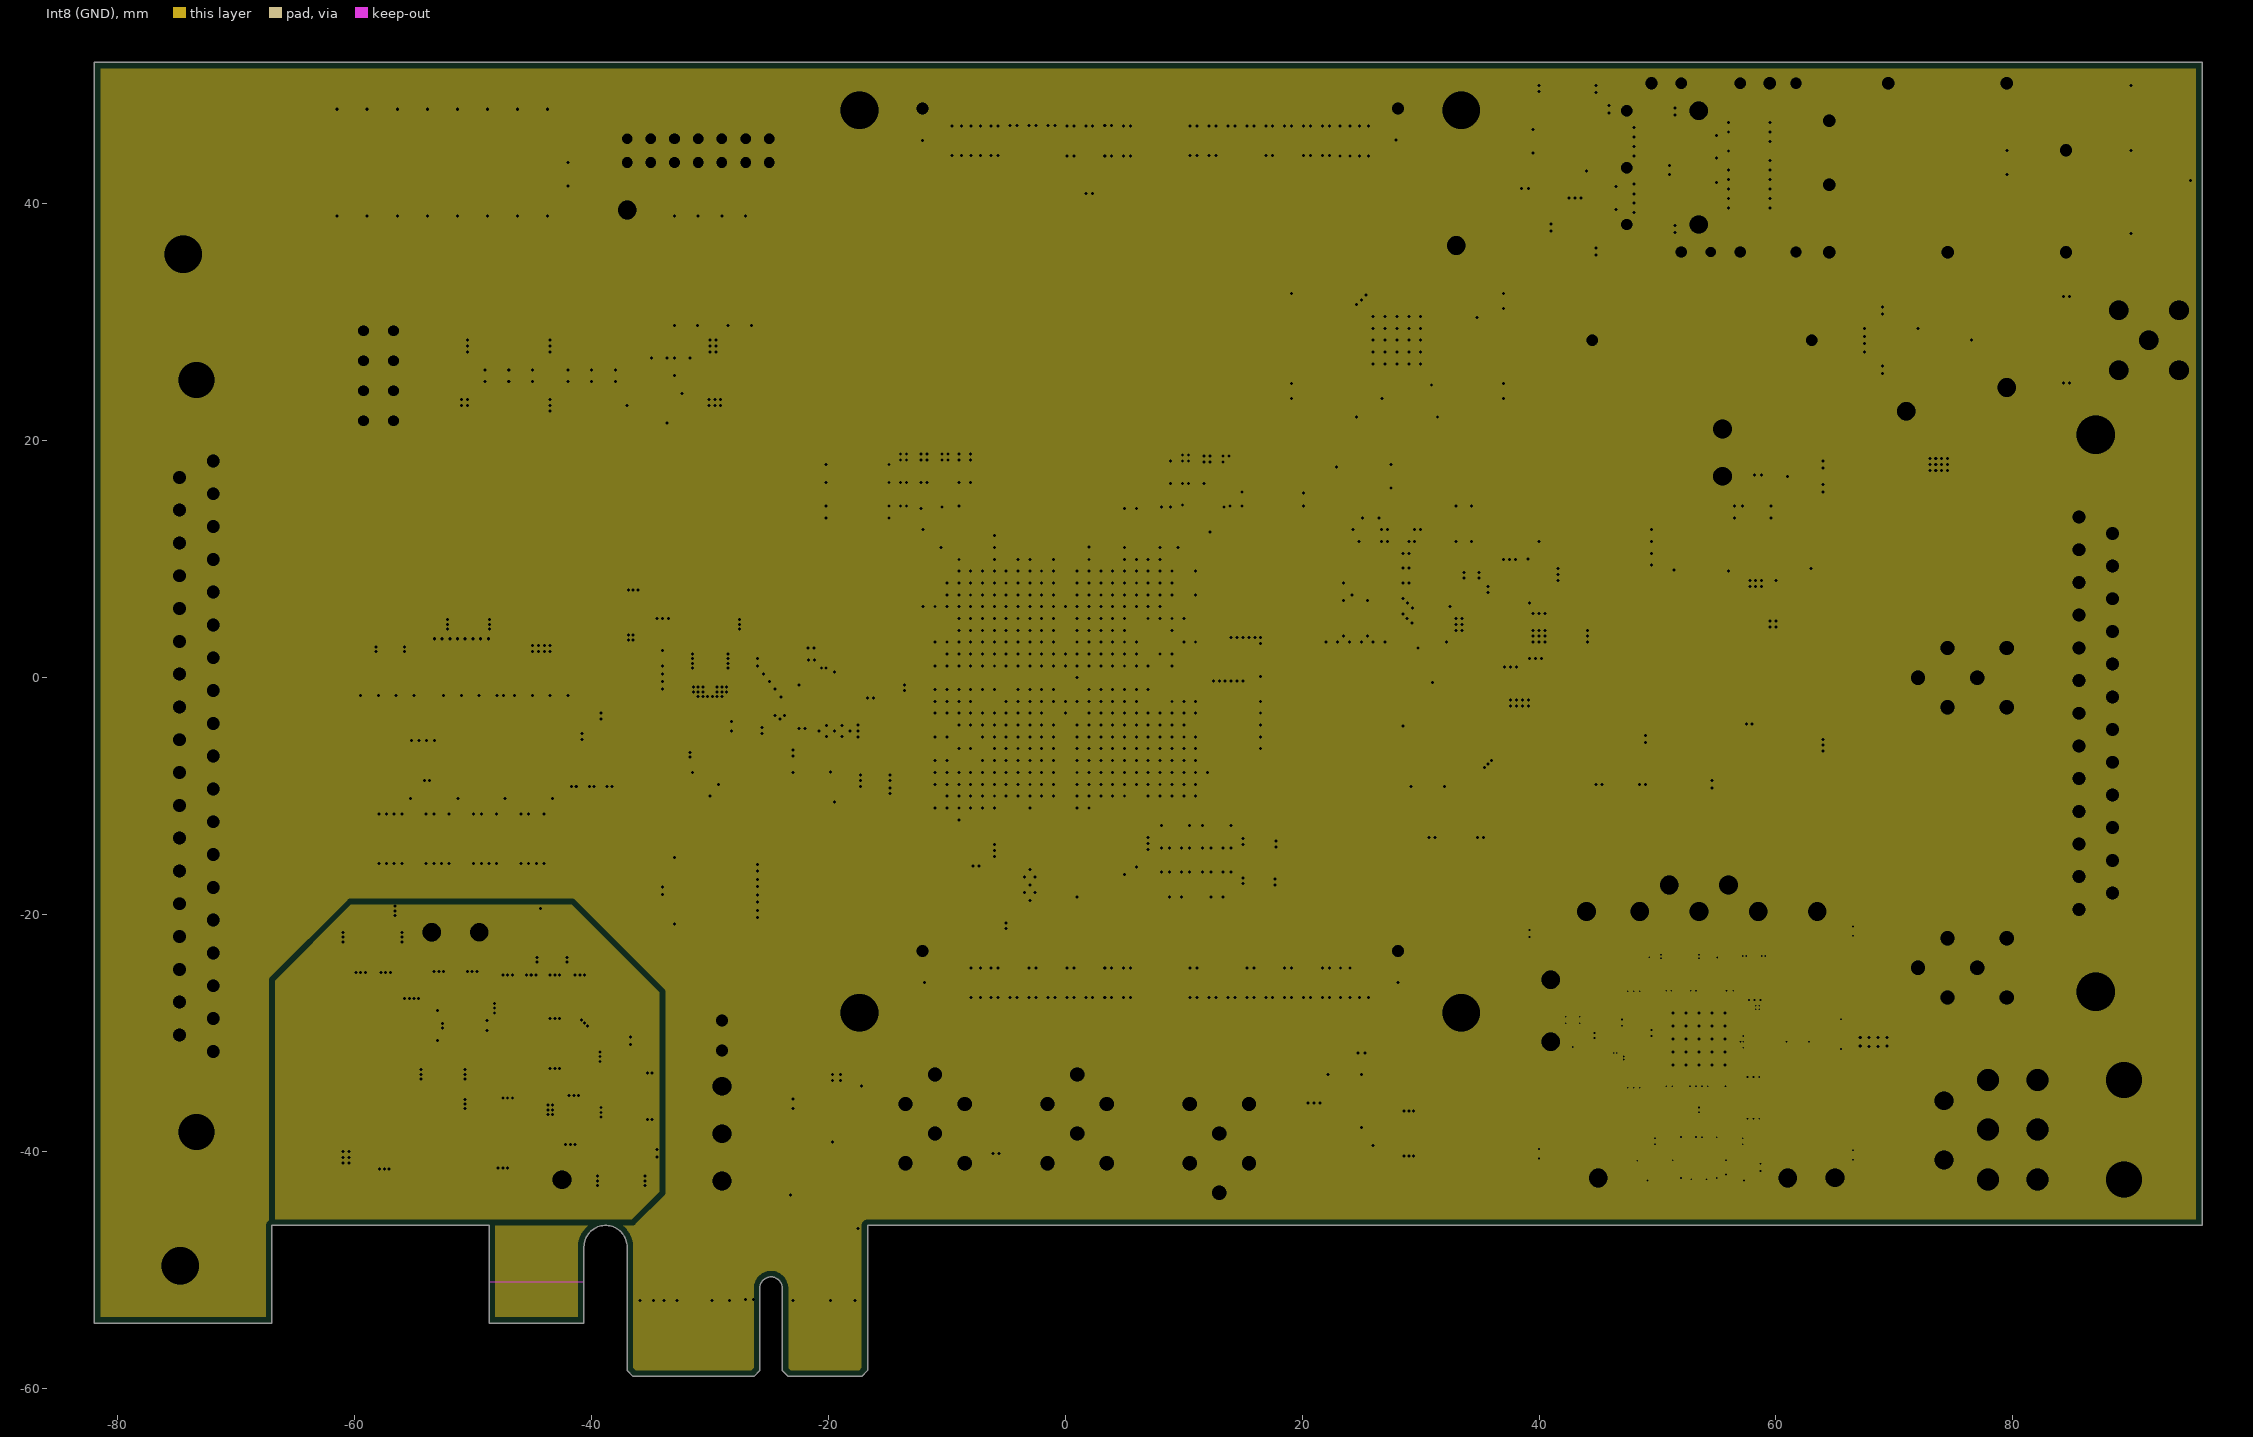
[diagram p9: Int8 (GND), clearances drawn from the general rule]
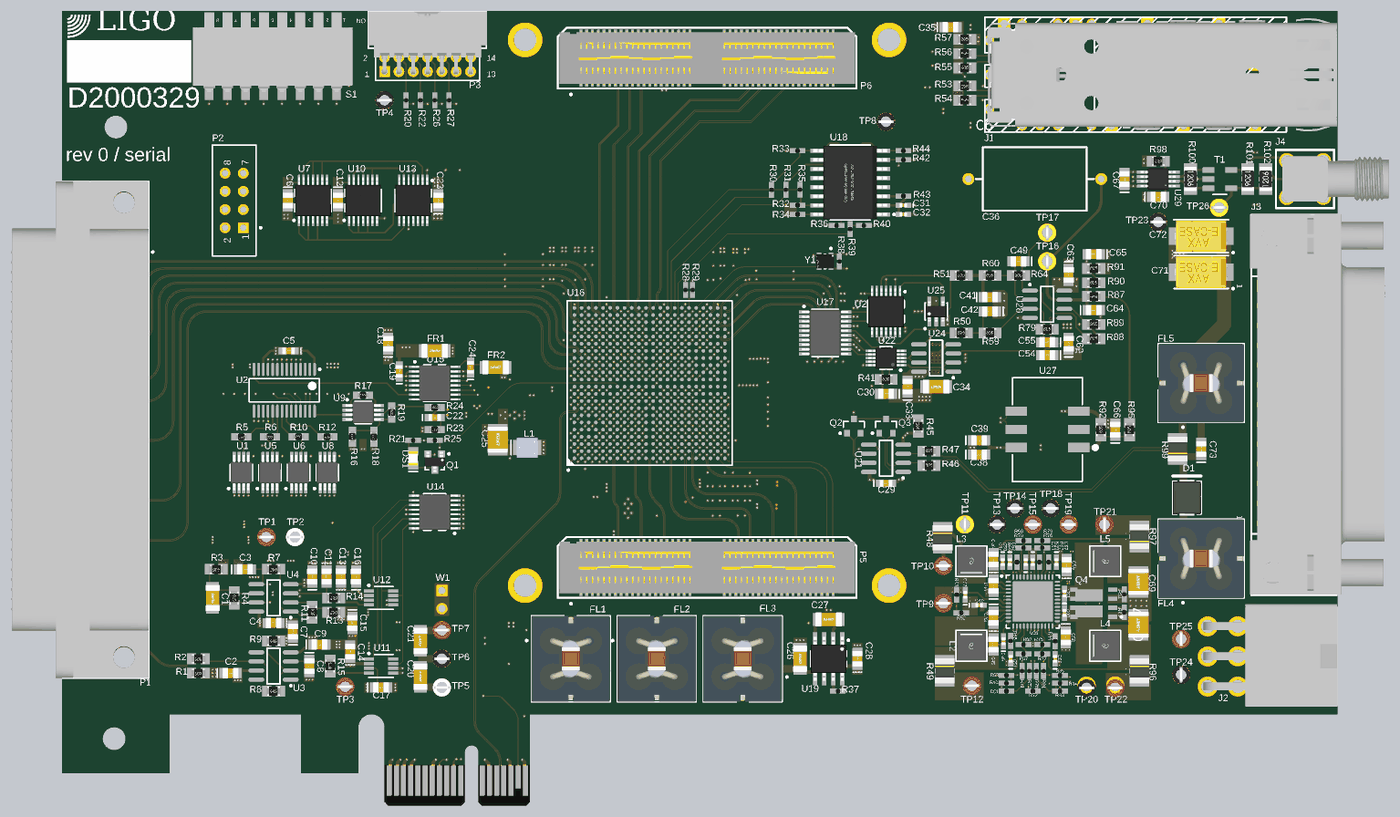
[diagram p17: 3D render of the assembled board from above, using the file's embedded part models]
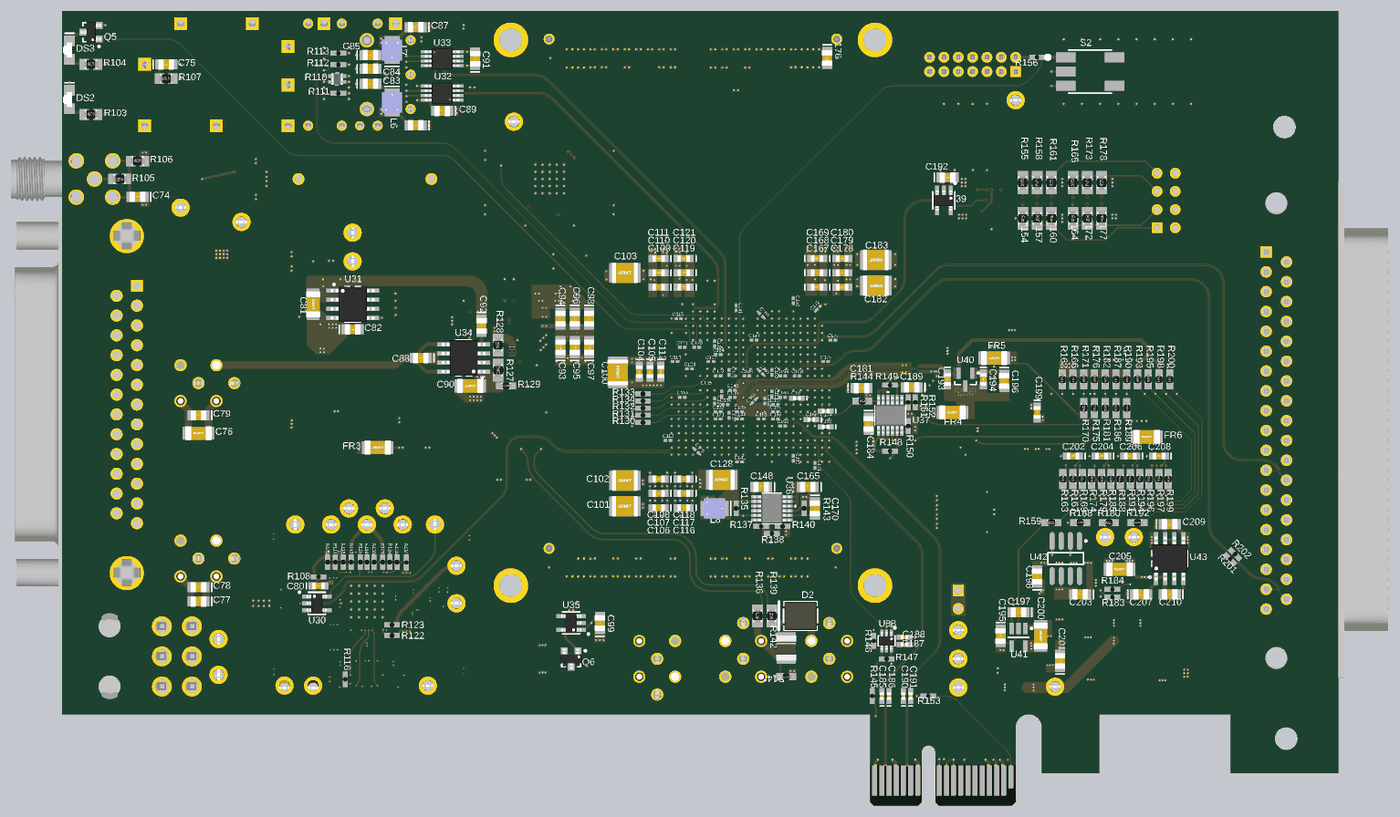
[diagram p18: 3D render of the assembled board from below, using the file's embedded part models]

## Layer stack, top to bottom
Top Solder: solder mask 0.0254, SM-001, Dk 4
Top Layer: signal copper 0.035
Dielectric 1: prepreg 0.0711, PP-006, Dk 4.1
Dielectric 2: prepreg 0.0711, PP-006, Dk 4.1
Int1 (GND): plane copper 0.0175, net (Multiple Nets)
Dielectric 3: core 0.127, Core-016, Dk 4.3
Int2 (Sign): signal copper 0.0175
Dielectric 4: prepreg 0.0711, PP-006, Dk 4.1
Dielectric 5: prepreg 0.0711, PP-006, Dk 4.1
Int3 (Sign): signal copper 0.0175
Dielectric 6: core 0.127, Core-016, Dk 4.3
Int4 (PWR): plane copper 0.0175, net (Multiple Nets)
Dielectric 7: prepreg 0.0711, PP-006, Dk 4.1
Dielectric 8: prepreg 0.0711, PP-006, Dk 4.1
Int5 (GND): plane copper 0.0175, net (Multiple Nets)
Dielectric 9: core 0.127, Core-016, Dk 4.3
Int6 (Sign): signal copper 0.0175
Dielectric 10: prepreg 0.0711, PP-006, Dk 4.1
Dielectric 11: prepreg 0.0711, PP-006, Dk 4.1
Int7 (Sign): signal copper 0.0175
Dielectric 12: core 0.127, Core-016, Dk 4.3
Int8 (GND): plane copper 0.0175, net (Multiple Nets)
Dielectric 13: prepreg 0.0711, PP-006, Dk 4.1
Dielectric 14: prepreg 0.0711, PP-006, Dk 4.1
Bottom Layer: signal copper 0.035
Bottom Solder: solder mask 0.0254, SM-001, Dk 4

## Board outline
-82,-54.5 -67,-54.5 -67,-46.25 -48.65,-46.25 -48.65,-54.5 -40.65,-54.5 -40.65,-48.075 cw(c-38.825,-48.075) -37,-48.075 -37,-58.5 -36.5,-59 -26.3,-59 -25.8,-58.5 -25.8,-51.55 cw(c-24.85,-51.55) -23.9,-51.55 -23.9,-58.5 -23.4,-59 -17.2,-59 -16.7,-58.5 -16.7,-46.25 96,-46.25 96,51.969 -82,51.969

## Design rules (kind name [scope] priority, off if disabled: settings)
Clearance [All] p1: gap=0.076 ignorepadtopadclearanceinfootprint=FALSE except(0: Arc-Hole Track-Hole SMDPad-Hole THPad-Hole Via-Hole Fill-Hole Poly-Hole Region-Hole Text-Hole)
DiffPairsRouting DiffPairsRouting_BGA [WithinRoom('FPGA')] p1: maxlimit=0.254 minlimit=0.076 mostfreqgap=0.127 toplayer_prefgap=0.076 toplayer_minwidth=0.127 toplayer_maxwidth=0.127 toplayer_prefwidth=0.127 midlayer3_mingap=0.127 midlayer3_maxgap=0.127 midlayer3_minwidth=0.076 midlayer3_maxwidth=0.076 midlayer3_prefwidth=0.076 midlayer4_mingap=0.127 midlayer4_maxgap=0.127 midlayer4_minwidth=0.076 midlayer4_maxwidth=0.076 midlayer4_prefwidth=0.076 midlayer5_mingap=0.127 midlayer5_maxgap=0.127 midlayer5_minwidth=0.076 midlayer5_maxwidth=0.076 midlayer5_prefwidth=0.076 midlayer6_mingap=0.127 midlayer6_maxgap=0.127 midlayer6_minwidth=0.076 midlayer6_maxwidth=0.076 midlayer6_prefwidth=0.076 bottomlayer_prefgap=0.076 bottomlayer_minwidth=0.127 bottomlayer_maxwidth=0.127 bottomlayer_prefwidth=0.127 impedanceprofiledriven=TRUE impedanceprofileid={C3FD04F3-F1EA-42A3-8B87-5CBABFB4C5AB} impedanceprofilevalue=100.000000 maxuncoupledlength=0.127
DiffPairsRouting [All] p2: maxlimit=0.152 minlimit=0.076 mostfreqgap=0.127 toplayer_prefgap=0.076 toplayer_minwidth=0.127 toplayer_maxwidth=0.381 toplayer_prefwidth=0.127 midlayer3_mingap=0.102 midlayer3_minwidth=0.076 midlayer3_maxwidth=0.076 midlayer3_prefwidth=0.076 midlayer4_mingap=0.102 midlayer4_minwidth=0.076 midlayer4_maxwidth=0.076 midlayer4_prefwidth=0.076 midlayer5_mingap=0.102 midlayer5_minwidth=0.076 midlayer5_maxwidth=0.076 midlayer5_prefwidth=0.076 midlayer6_mingap=0.102 midlayer6_minwidth=0.076 midlayer6_maxwidth=0.076 midlayer6_prefwidth=0.076 bottomlayer_prefgap=0.076 bottomlayer_minwidth=0.127 bottomlayer_maxwidth=0.381 bottomlayer_prefwidth=0.127 impedanceprofiledriven=TRUE impedanceprofileid={C3FD04F3-F1EA-42A3-8B87-5CBABFB4C5AB} impedanceprofilevalue=100.000000 maxuncoupledlength=0.127
FabricationTestPointUsage TestPointUsage [All] p1: valid=0 allowmultiple=FALSE
FabricationTestpoint Testpoint [All] p1: side=3 testpointundercomponent=TRUE minsize=1.016 maxsize=2.54 preferedsize=1.524 minholesize=0.508 maxholesize=1.016 preferedholesize=0.813 testpointgrid=0.025 allowsidetop=TRUE allowsidebottom=TRUE usegrid=TRUE gridtolerance=0
Height "PCI Express, Page 84, \"Component Height Constraints\" for solder side" [OnBottomLayer] p1: minheight=0 maxheight=2.67 prefheight=2.67
Height "PCI Express, Page 84, \"Component Height Constraints\" for component side" [OnTopLayer] p2: minheight=0 maxheight=14.47 prefheight=14.47
MatchedLengths MatchedLengths_RX [InDifferentialPair('PCIE.PCIE_RX0')] p1: tolerance=0.025 checknetsindiffpair=TRUE checkdiffpairvsdiffpair=FALSE checkxsignals=FALSE checkothers=FALSE
MatchedLengths MatchedLengths_TX [InDifferentialPair('PCIE.PCIE_TX0')] p2: tolerance=0.025 checknetsindiffpair=TRUE checkdiffpairvsdiffpair=FALSE checkxsignals=FALSE checkothers=FALSE
MatchedLengths MatchedLengths_CLK [InDifferentialPair('PCIE.PCIE_CLK')] p3: tolerance=0.025 checknetsindiffpair=TRUE checkdiffpairvsdiffpair=FALSE checkxsignals=FALSE checkothers=FALSE
PlaneClearance [All] p1: clearance=0
PlaneConnect [All] p1: planeconnectstyle=Direct reliefexpansion=0.508 reliefentries=4 reliefconductorwidth=0.254 reliefairgap=0.254
PolygonConnect PolygonDirectConnect [All vs IsPolygon] p1: connectstyle=Direct reliefconductorwidth=0.254 reliefentries=4 polygonreliefangle="90 Angle" airgapwidth=0.254
PolygonConnect [All] p2: connectstyle=Relief reliefconductorwidth=0.254 reliefentries=4 polygonreliefangle="90 Angle" airgapwidth=0.254
RoomDefinition FPGA [InComponentClass('FPGA')] p1: confinementstyle=ConfineIn formatcopy=TRUE lockcomponents=FALSE outline 13.625,13.156 -13.625,13.156 -13.625,-13.625 13.625,-13.625
RoutingVias RoutingVias_BGA [WithinRoom('FPGA')] p1: holewidth=0.254 width=0.483 viastyle="Through Hole" minholewidth=0.254 minwidth=0.483 maxholewidth=0.254 maxwidth=0.483
RoutingVias [All] p2: holewidth=0.254 width=0.508 viastyle="Through Hole" minholewidth=0.203 minwidth=0.406 maxholewidth=0.711 maxwidth=1.27
SilkToSolderMaskClearance SilkscreenOverComponentPads [IsPad] p1: minsilkscreentomaskgap=0.254 clearancetoexposedcopper=TRUE
SolderMaskExpansion [All] p1: expansion=0 istentingtop=FALSE
Width [All] p1: maxlimit=5 minlimit=0.076 preferedwidth=0.254
23 further rules are at their usual default settings.

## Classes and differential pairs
net class XMUX[3..0]: SQSPI.XMUX0 SQSPI.XMUX1 SQSPI.XMUX2 SQSPI.XMUX3
net class SW[10..1]: CONFIG.SW1 CONFIG.SW2 CONFIG.SW3 CONFIG.SW4 CONFIG.SW5 CONFIG.SW6 CONFIG.SW7 CONFIG.SW8 CONFIG.SW9 CONFIG.SW10
polygon class "No Thermals": SW_PWR_2
component class FPGA: R144 U1_B U16
net class JTAG[1..5]: JTAG1 JTAG2 JTAG3 JTAG4 JTAG5
differential pair XADC.XADC_REF: +XADC.XADC_REF_P -XADC.XADC_REF_N
differential pair S33_48.S48: +S33_48.S48_P -S33_48.S48_N
differential pair S33_48.S47: +S33_48.S47_P -S33_48.S47_N
differential pair S33_48.S46: +S33_48.S46_P -S33_48.S46_N
differential pair S33_48.S45: +S33_48.S45_P -S33_48.S45_N
differential pair S33_48.S44: +S33_48.S44_P -S33_48.S44_N
differential pair S33_48.S43: +S33_48.S43_P -S33_48.S43_N
differential pair S33_48.S42: +S33_48.S42_P -S33_48.S42_N
differential pair S33_48.S41: +S33_48.S41_P -S33_48.S41_N
differential pair S33_48.S40: +S33_48.S40_P -S33_48.S40_N
differential pair S33_48.S39: +S33_48.S39_P -S33_48.S39_N
differential pair S33_48.S38: +S33_48.S38_P -S33_48.S38_N
differential pair S33_48.S37: +S33_48.S37_P -S33_48.S37_N
differential pair S33_48.S36: +S33_48.S36_P -S33_48.S36_N
differential pair S33_48.S35: +S33_48.S35_P -S33_48.S35_N
differential pair S33_48.S34: +S33_48.S34_P -S33_48.S34_N
differential pair S33_48.S33: +S33_48.S33_P -S33_48.S33_N
differential pair XOCTR: +XOCTR_P -XOCTR_N
differential pair EXT_SYNC.EXTSYNC: +EXT_SYNC.EXTSYNC_P -EXT_SYNC.EXTSYNC_N
differential pair XOCTRL: +XOCTRL_P -XOCTRL_N
differential pair DUOTONE: +DUOTONE_P -DUOTONE_N
differential pair X1: +X1_P -X1_N
differential pair REFCLK: +REFCLK_P -REFCLK_N
differential pair BACKPLANE.SCLK: +BACKPLANE.SCLK_P -BACKPLANE.SCLK_N
differential pair BACKPLANE.CLK5: +BACKPLANE.CLK5_P -BACKPLANE.CLK5_N
differential pair BACKPLANE.X5: +BACKPLANE.X5_P -BACKPLANE.X5_N
differential pair BACKPLANE.X3: +BACKPLANE.X3_P -BACKPLANE.X3_N
differential pair PER0: +PER0_P -PER0_N
differential pair POWER.PWRSYNC: +POWER.PWRSYNC_P -POWER.PWRSYNC_N
differential pair DAC_REF.REFCLK: +DAC_REF.REFCLK_P -DAC_REF.REFCLK_N
differential pair DAC_REF.INVSYNC: +DAC_REF.INVSYNC_P -DAC_REF.INVSYNC_N
differential pair DAC_REF.DSYNC: +DAC_REF.DSYNC_P -DAC_REF.DSYNC_N
differential pair DAC_REF.DSCLK: +DAC_REF.DSCLK_P -DAC_REF.DSCLK_N
differential pair DAC_REF.DOUT1: +DAC_REF.DOUT1_P -DAC_REF.DOUT1_N
differential pair DAC_REF.DOUT0: +DAC_REF.DOUT0_P -DAC_REF.DOUT0_N
differential pair CLOCK.SYNC: +CLOCK.SYNC_P -CLOCK.SYNC_N
differential pair CLOCK.OSCCLK: +CLOCK.OSCCLK_P -CLOCK.OSCCLK_N
differential pair CLOCK.CNTROUT: +CLOCK.CNTROUT_P -CLOCK.CNTROUT_N
differential pair CLOCK.AIN: +CLOCK.AIN_P -CLOCK.AIN_N
differential pair CLOCK.ACNV: +CLOCK.ACNV_P -CLOCK.ACNV_N
differential pair CLOCK.ACLK: +CLOCK.ACLK_P -CLOCK.ACLK_N
differential pair SFPIN.SYNCOUT: +SFPIN.SYNCOUT_P -SFPIN.SYNCOUT_N
differential pair SFPIN.SYNCIN: +SFPIN.SYNCIN_P -SFPIN.SYNCIN_N
differential pair PCIE.PCIE_TX0: +PCIE.PCIE_TX0_P -PCIE.PCIE_TX0_N
differential pair PCIE.PCIE_RX0: +PCIE.PCIE_RX0_P -PCIE.PCIE_RX0_N
differential pair PCIE.PCIE_CLK: +PCIE.PCIE_CLK_P -PCIE.PCIE_CLK_N
differential pair BACKPLANE.X1: +BACKPLANE.X1_P -BACKPLANE.X1_N
differential pair BACKPLANE.DOUT: +BACKPLANE.DOUT_P -BACKPLANE.DOUT_N
differential pair BACKPLANE.DIN: +BACKPLANE.DIN_P -BACKPLANE.DIN_N
differential pair BACKPLANE.CS: +BACKPLANE.CS_P -BACKPLANE.CS_N
differential pair BACKPLANE.CLK9: +BACKPLANE.CLK9_P -BACKPLANE.CLK9_N
differential pair BACKPLANE.CLK8: +BACKPLANE.CLK8_P -BACKPLANE.CLK8_N
differential pair BACKPLANE.CLK7: +BACKPLANE.CLK7_P -BACKPLANE.CLK7_N
differential pair BACKPLANE.CLK6: +BACKPLANE.CLK6_P -BACKPLANE.CLK6_N
differential pair BACKPLANE.CLK4: +BACKPLANE.CLK4_P -BACKPLANE.CLK4_N
differential pair BACKPLANE.CLK3: +BACKPLANE.CLK3_P -BACKPLANE.CLK3_N
differential pair BACKPLANE.CLK2: +BACKPLANE.CLK2_P -BACKPLANE.CLK2_N
differential pair BACKPLANE.CLK1: +BACKPLANE.CLK1_P -BACKPLANE.CLK1_N
differential pair BACKPLANE.CLK0: +BACKPLANE.CLK0_P -BACKPLANE.CLK0_N
differential pair T1_11.T11: +T1_11.T11_P -T1_11.T11_N
differential pair T1_11.T10: +T1_11.T10_P -T1_11.T10_N
differential pair T1_11.T9: +T1_11.T9_P -T1_11.T9_N
differential pair T1_11.T8: +T1_11.T8_P -T1_11.T8_N
differential pair T1_11.T7: +T1_11.T7_P -T1_11.T7_N
differential pair T1_11.T6: +T1_11.T6_P -T1_11.T6_N
differential pair T1_11.T5: +T1_11.T5_P -T1_11.T5_N
differential pair T1_11.T4: +T1_11.T4_P -T1_11.T4_N
differential pair T1_11.T3: +T1_11.T3_P -T1_11.T3_N
differential pair T1_11.T2: +T1_11.T2_P -T1_11.T2_N
differential pair T1_11.T1: +T1_11.T1_P -T1_11.T1_N
differential pair S49_64.S64: +S49_64.S64_P -S49_64.S64_N
differential pair S49_64.S63: +S49_64.S63_P -S49_64.S63_N
differential pair S49_64.S62: +S49_64.S62_P -S49_64.S62_N
differential pair S49_64.S61: +S49_64.S61_P -S49_64.S61_N
differential pair S49_64.S60: +S49_64.S60_P -S49_64.S60_N
differential pair S49_64.S59: +S49_64.S59_P -S49_64.S59_N
differential pair S49_64.S58: +S49_64.S58_P -S49_64.S58_N
differential pair S49_64.S57: +S49_64.S57_P -S49_64.S57_N
differential pair S49_64.S56: +S49_64.S56_P -S49_64.S56_N
differential pair S49_64.S55: +S49_64.S55_P -S49_64.S55_N
differential pair S49_64.S54: +S49_64.S54_P -S49_64.S54_N
differential pair S49_64.S53: +S49_64.S53_P -S49_64.S53_N
differential pair S49_64.S52: +S49_64.S52_P -S49_64.S52_N
differential pair S49_64.S51: +S49_64.S51_P -S49_64.S51_N
differential pair S49_64.S50: +S49_64.S50_P -S49_64.S50_N
differential pair S49_64.S49: +S49_64.S49_P -S49_64.S49_N
differential pair S17_32.S32: +S17_32.S32_P -S17_32.S32_N
differential pair S17_32.S31: +S17_32.S31_P -S17_32.S31_N
differential pair S17_32.S30: +S17_32.S30_P -S17_32.S30_N
differential pair S17_32.S29: +S17_32.S29_P -S17_32.S29_N
differential pair S17_32.S28: +S17_32.S28_P -S17_32.S28_N
differential pair S17_32.S27: +S17_32.S27_P -S17_32.S27_N
differential pair S17_32.S26: +S17_32.S26_P -S17_32.S26_N
differential pair S17_32.S25: +S17_32.S25_P -S17_32.S25_N
differential pair S17_32.S24: +S17_32.S24_P -S17_32.S24_N
differential pair S17_32.S23: +S17_32.S23_P -S17_32.S23_N
differential pair S17_32.S22: +S17_32.S22_P -S17_32.S22_N
differential pair S17_32.S21: +S17_32.S21_P -S17_32.S21_N
differential pair S17_32.S20: +S17_32.S20_P -S17_32.S20_N
differential pair S17_32.S19: +S17_32.S19_P -S17_32.S19_N
differential pair S17_32.S18: +S17_32.S18_P -S17_32.S18_N
differential pair S17_32.S17: +S17_32.S17_P -S17_32.S17_N
differential pair S1_16.S16: +S1_16.S16_P -S1_16.S16_N
differential pair S1_16.S15: +S1_16.S15_P -S1_16.S15_N
differential pair S1_16.S14: +S1_16.S14_P -S1_16.S14_N
differential pair S1_16.S13: +S1_16.S13_P -S1_16.S13_N
differential pair S1_16.S12: +S1_16.S12_P -S1_16.S12_N
differential pair S1_16.S11: +S1_16.S11_P -S1_16.S11_N
differential pair S1_16.S10: +S1_16.S10_P -S1_16.S10_N
differential pair S1_16.S9: +S1_16.S9_P -S1_16.S9_N
differential pair S1_16.S8: +S1_16.S8_P -S1_16.S8_N
differential pair S1_16.S7: +S1_16.S7_P -S1_16.S7_N
differential pair S1_16.S6: +S1_16.S6_P -S1_16.S6_N
differential pair S1_16.S5: +S1_16.S5_P -S1_16.S5_N
differential pair S1_16.S4: +S1_16.S4_P -S1_16.S4_N
differential pair S1_16.S3: +S1_16.S3_P -S1_16.S3_N
differential pair S1_16.S2: +S1_16.S2_P -S1_16.S2_N
differential pair S1_16.S1: +S1_16.S1_P -S1_16.S1_N

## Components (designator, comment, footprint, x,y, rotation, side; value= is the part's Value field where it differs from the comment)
C1 "33n" CC3216-1206 -61,-30 r90 top (schematic designator C72)
C2 "1u" CC2013-0805 -58.5,-40.5 r0 top (schematic designator C161)
C3 "33n" CC2013-0805 -56.5,-26 r0 top (schematic designator C51)
C4 "1u" CC2013-0805 -52.5,-33.5 r180 top (schematic designator C39)
C5 "1u" CC1608-0603 -50.4,4.5 r180 top (schematic designator C160)
C6 "100n" CC2013-0805 -50.5,25.5 r270 top (schematic designator C148)
C7 "10u" CC2013-0805 -49.8,-34.7 r90 top (schematic designator C164)
C8 "1n" CC2013-0805 -47.5,-39.5 r270 top (schematic designator C167)
C9 "1u" CC2013-0805 -46.1,-36.5 r0 top (schematic designator C168)
C10 "1u" CC2013-0805 -47.1,-27 r90 top (schematic designator C50)
C11 "33n" CC2013-0805 -45.1,-27 r270 top (schematic designator C40)
C12 "100n" CC2013-0805 -43.5,25.5 r270 top (schematic designator C147)
C13 "100n" CC2013-0805 -43.1,-27 r90 top (schematic designator C38)
C14 "100n" CC2013-0805 -41.8,-37.5 r90 top (schematic designator C163)
C15 "10u" CC2013-0805 -41.5,-33.5 r270 top (schematic designator C37)
C16 "100n" CC2013-0805 -41,-27 r90 top (schematic designator C36)
C17 "100n" CC2013-0805 -37.5,-42.5 r0 top (schematic designator C165)
C18 "10u" CC2013-0805 -36.5,5.5 r90 top (schematic designator C175)
C19 "1u" CC1608-0603 -34.95,1.625 r90 top (schematic designator C157)
C20 "47u" CC3216-1206 -32,-41 r270 top (schematic designator C210)
C21 "47u" CC3216-1206 -32,-36 r90 top (schematic designator C209)
C22 "1n" CC1608-0603 -30,-4.8 r0 top (schematic designator C155)
C23 "100n" CC2013-0805 -29.5,25.5 r90 top (schematic designator C149)
C24 "1u" CC1608-0603 -25,2.203 r90 top (schematic designator C158)
C25 "100u" CC3225-1210 -21.2,-7.9 r270 top (schematic designator C94)
C26 "10u" CC3216-1206 21,-38.5 r270 top (schematic designator C180)
C27 "10u" CC3216-1206 25,-33 r0 top (schematic designator C177)
C28 "100n" CC2013-0805 29,-38.5 r90 top (schematic designator C176)
C29 "1u" CC1608-0603 33,-14 r0 top (schematic designator C202)
C30 "1u" CC2013-0805 33,-1.5 r180 top (schematic designator C13)
C31 "100n" CC1005-0402 35.42,24.825 r180 top (schematic designator C33)
C32 "100n" CC1005-0402 35.42,23.555 r180 top (schematic designator C34)
C33 "1u" CC2013-0805 36,-0.5 r90 top (schematic designator C5)
C34 "10u" CC3216-1206 40,-0.5 r180 top (schematic designator C10)
C35 "10n" CC2013-0805 42,49.7 r0 top (schematic designator C12)
C36 "470n" CA053035 44.5,28.5 r0 top locked (schematic designator C16)
C37 "1uF" CC1005-0402 44.062,-29.562 r90 top (schematic designator C196)
C38 "10u" CC2013-0805 46,-10 r0 top (schematic designator C15)
C39 "100n" CC2013-0805 46,-8 r0 top (schematic designator C14)
C40 "1uF" CC1005-0402 46,-31 r0 top (schematic designator C200)
C41 "1n'" CC2013-0805 47.5,12 r0 top (schematic designator C19)
C42 "1n" CC2013-0805 47.5,10 r180 top (schematic designator C21)
C43 "10uF" CC2013-0805 48,-32.75 r270 top (schematic designator C42)
C44 "10uF" CC2013-0805 48,-28.3 r90 top (schematic designator C43)
C45 "10uF" CC2013-0805 48,-36.5 r270 top (schematic designator C195)
C46 "10uF" CC2013-0805 48,-24.6 r90 top (schematic designator C193)
C47 "100n" CC1005-0402 49.3,-25 r270 top (schematic designator C192)
C48 "100n" CC1005-0402 49.4,-36.05 r90 top (schematic designator C194)
C49 "NL" CC2013-0805 51.5,17 r180 top (schematic designator C17)
C50 "1.8nF" CC1005-0402 50.3,-25 r270 top (schematic designator C198)
C51 "1.8nF" CC1005-0402 50.4,-38.5 r90 top (schematic designator C199)
C52 "1uF" CC1005-0402 52.5,-25 r90 top (schematic designator C190)
C53 "1uF" CC1005-0402 53.5,-25 r270 top (schematic designator C201)
C54 "100n" CC2013-0805 55.5,3.9 r180 top (schematic designator C25)
C55 "NL" CC2013-0805 55.5,5.7 r180 top (schematic designator C24)
C56 "5.6nF" CC1005-0402 56.6,-38.5 r90 top (schematic designator C197)
C57 "2.7nF" CC1005-0402 56.8,-25 r270 top (schematic designator C191)
C58 "10uF" CC2013-0805 58.1,-35.5 r270 top (schematic designator C49)
C59 "10uF" CC2013-0805 58.2,-25.4 r90 top (schematic designator C44)
C60 "100n" CC1005-0402 57.902,-32.1 r270 top (schematic designator C189)
C61 "100n" CC1005-0402 57.902,-29.4 r90 top (schematic designator C185)
C62 "100n" CC2013-0805 58.5,5.5 r90 top (schematic designator C22)
C63 "100n" CC2013-0805 58.5,15.1 r270 top (schematic designator C18)
C64 "10n" CC2013-0805 62,10.2 r0 top (schematic designator C153)
C65 "100n" CC2013-0805 62,18 r180 top (schematic designator C23)
C66 "1n" CC2013-0805 65,-6.5 r90 top (schematic designator C20)
C67 "1u" CC2013-0805 66.3,28.5 r90 top (schematic designator C54)
C68 "47uF" CC3225-1210 68.25,-33.75 r90 top (schematic designator C187)
C69 "100uF" CC3225-1210 68.25,-27.75 r90 top (schematic designator C186)
C70 "10n" CC2013-0805 71,26 r0 top (schematic designator C64)
C71 "68u" TC7343-2917 77,15.5 r180 top (schematic designator C213)
C72 "68u" TC7343-2917 77,20.526 r180 top (schematic designator C214)
C73 "10uF" CC2013-0805 77,-9.2 r90 top (schematic designator C48)
C74 "10u" CC2013-0805 85.5,26 r0 bottom (schematic designator C57)
C75 "100n" CC2013-0805 81.5,44.5 r180 bottom (schematic designator C11)
C76 "47u" CC3216-1206 77,-7 r180 bottom (schematic designator C208)
C77 "10uF" CC2013-0805 77,-30.5 r0 bottom (schematic designator C46)
C78 "10uF" CC2013-0805 77,-28.5 r0 bottom (schematic designator C45)
C79 "10uF" CC2013-0805 77,-4.5 r0 bottom (schematic designator C47)
C80 "0.1u" CC1608-0603 60.25,-28.312 r180 bottom (schematic designator C41)
C81 "10u" CC3216-1206 61,11 r270 bottom (schematic designator C2)
C82 "1u" CC2013-0805 55.5,7.5 r180 bottom (schematic designator C3)
C83 "100n" CC2013-0805 53,41.8 r180 bottom (schematic designator C9)
C84 "100n" CC2013-0805 53,43.9 r180 bottom (schematic designator C4)
C85 "10u" CC2013-0805 53,45.8 r180 bottom (schematic designator C8)
C86 "100n" CC2013-0805 46.7,36 r0 bottom (schematic designator C6)
C87 "10u" CC2013-0805 46.7,49.7 r0 bottom (schematic designator C7)
C88 "100n" CC2013-0805 46,3.5 r0 bottom (schematic designator C215)
C89 "100n" CC2013-0805 42.995,38 r0 bottom (schematic designator C73)
C90 "10u" CC3216-1206 39.1,-0.4 r0 bottom (schematic designator C212)
C91 "100n" CC2013-0805 38.4,45.3 r90 bottom (schematic designator C81)
C92 "10n" CC2013-0805 37.5,8 r270 bottom (schematic designator C211)
C93 "100n" CC2013-0805 26.5,5 r90 bottom (schematic designator C31)
C94 "100n" CC2013-0805 26.5,9 r270 bottom (schematic designator C29)
C95 "100n" CC2013-0805 24.5,5 r90 bottom (schematic designator C30)
C96 "100n" CC2013-0805 24.5,9 r270 bottom (schematic designator C28)
C97 "100n" CC2013-0805 22.5,5 r90 bottom (schematic designator C26)
C98 "100n" CC2013-0805 22.5,9 r270 bottom (schematic designator C27)
C99 "100n" CC2013-0805 21,-33.5 r90 bottom (schematic designator C1)
C100 "47uF" CC3225-1210 18.5,1.5 r270 bottom (schematic designator C115)
C101 "100uF" CC3225-1210 17.5,-17.2 r180 bottom (schematic designator C106)
C102 "330uF" CC3225-1210 17.5,-13.6 r180 bottom (schematic designator C103)
C103 "100uF" CC3225-1210 17.5,15.4 r180 bottom (schematic designator C127)
C104 "4.7uF" CC1608-0603 15.5,1.6 r270 bottom (schematic designator C111)
C105 "4.7uF" CC1608-0603 14,1.6 r270 bottom (schematic designator C108)
C106 "4.7uF" CC1608-0603 12.8,-17.4 r0 bottom (schematic designator C79)
C107 "4.7uF" CC1608-0603 12.8,-15.4 r0 bottom (schematic designator C77)
C108 "4.7uF" CC1608-0603 12.8,-13.4 r0 bottom (schematic designator C75)
C109 "4.7uF" CC1608-0603 12.8,13.4 r0 bottom (schematic designator C113)
C110 "4.7uF" CC1608-0603 12.8,15.4 r0 bottom (schematic designator C133)
C111 "4.7uF" CC1608-0603 12.8,17.4 r0 bottom (schematic designator C125)
C112 "4.7uF" CC1608-0603 12.5,1.6 r270 bottom (schematic designator C109)
C113 "0.47uF" CAPC0603X33X15NL03T05 11.5,-8 r180 bottom (schematic designator C129)
C114 "0.47uF" CAPC0603X33X15NL03T05 10.5,3 r0 bottom (schematic designator C56)
C115 "0.47uF" CAPC0603X33X15NL03T05 10,9 r180 bottom (schematic designator C131)
C116 "4.7uF" CC1608-0603 9.3,-17.4 r0 bottom (schematic designator C76)
C117 "4.7uF" CC1608-0603 9.3,-15.4 r0 bottom (schematic designator C78)
C118 "4.7uF" CC1608-0603 9.3,-13.4 r0 bottom (schematic designator C80)
C119 "4.7uF" CC1608-0603 9.3,13.4 r0 bottom (schematic designator C120)
C120 "4.7uF" CC1608-0603 9.3,15.4 r0 bottom (schematic designator C119)
C121 "4.7uF" CC1608-0603 9.3,17.4 r0 bottom (schematic designator C132)
C122 "0.47uF" CAPC0603X33X15NL03T05 9.5,-2 r180 bottom (schematic designator C55)
C123 "0.47uF" CAPC0603X33X15NL03T05 9.5,5 r180 bottom (schematic designator C53)
C124 "0.47uF" CAPC0603X33X15NL03T05 8.5,2 r180 bottom (schematic designator C52)
C125 "0.47uF" CAPC0603X33X15NL03T05 7.5,-9.5 r45 bottom (schematic designator C130)
C126 "0.47uF" CAPC0603X33X15NL03T05 7.5,5 r180 bottom (schematic designator C152)
C127 "0.47uF" CAPC0603X33X15NL03T05 5.5,3 r180 bottom (schematic designator C62)
C128 "100u" CC3225-1210 4,-13.5 r180 bottom (schematic designator C88)
C129 "0.47uF" CAPC0603X33X15NL03T05 5,-2.5 r270 bottom (schematic designator C65)
C130 "0.47uF" CAPC0603X33X15NL03T05 5,5.5 r270 bottom (schematic designator C110)
C131 "0.47uF" CAPC0603X33X15NL03T05 4.5,-5 r0 bottom (schematic designator C146)
C132 "0.47uF" CAPC0603X33X15NL03T05 4.5,1 r0 bottom (schematic designator C128)
C133 "0.47uF" CAPC0603X33X15NL03T05 4.5,-4 r180 bottom (schematic designator C67)
C134 "0.47uF" CAPC0603X33X15NL03T05 4.5,4 r180 bottom (schematic designator C63)
C135 "0.47uF" CAPC0603X33X15NL03T05 4,-1.5 r90 bottom (schematic designator C92)
C136 "0.47uF" CAPC0603X33X15NL03T05 3.5,-3 r180 bottom (schematic designator C145)
C137 "0.47uF" CAPC0603X33X15NL03T05 3,-4.5 r270 bottom (schematic designator C68)
C138 "0.47uF" CAPC0603X33X15NL03T05 3,1.5 r270 bottom (schematic designator C107)
C139 "0.47uF" CAPC0603X33X15NL03T05 2.5,-2 r180 bottom (schematic designator C74)
C140 "0.47uF" CAPC0603X33X15NL03T05 2.5,-1 r180 bottom (schematic designator C104)
C141 "0.47uF" CAPC0603X33X15NL03T05 2,10.5 r270 bottom (schematic designator C117)
C142 "0.47uF" CAPC0603X33X15NL03T05 1.5,-11 r0 bottom (schematic designator C61)
C143 "0.47uF" CAPC0603X33X15NL03T05 1.5,-4 r0 bottom (schematic designator C71)
C144 "0.47uF" CAPC0603X33X15NL03T05 1.5,-5 r180 bottom
C145 "0.47uF" CAPC0603X33X15NL03T05 0.5,1 r0 bottom (schematic designator C97)
C146 "0.47uF" CAPC0603X33X15NL03T05 -0.5,-2.5 r315 bottom (schematic designator C188)
C147 "0.47uF" CAPC0603X33X15NL03T05 -0.5,5.998 r180 bottom (schematic designator C116)
C148 "1u" CC2013-0805 -1.5,-14.5 r0 bottom (schematic designator C89)
C149 "0.47uF" CAPC0603X33X15NL03T05 -1.5,1.5 r225 bottom (schematic designator C85)
C150 "0.47uF" CAPC0603X33X15NL03T05 -1.5,9.5 r225 bottom (schematic designator C118)
C151 "0.47uF" CAPC0603X33X15NL03T05 -1.5,-5 r180 bottom (schematic designator C143)
C152 "0.47uF" CAPC0603X33X15NL03T05 -2,-2.5 r90 bottom (schematic designator C134)
C153 "0.47uF" CAPC0603X33X15NL03T05 -3,-1.5 r90 bottom (schematic designator C105)
C154 "0.47uF" CAPC0603X33X15NL03T05 -3,1.5 r90 bottom (schematic designator C114)
C155 "0.47uF" CAPC0603X33X15NL03T05 -3.5,-4 r0 bottom (schematic designator C142)
C156 "0.47uF" CAPC0603X33X15NL03T05 -3.5,-5 r180 bottom (schematic designator C70)
C157 "0.47uF" CAPC0603X33X15NL03T05 -3.5,-3 r180 bottom (schematic designator C66)
C158 "0.47uF" CAPC0603X33X15NL03T05 -4.5,-6 r0 bottom (schematic designator C135)
C159 "0.47uF" CAPC0603X33X15NL03T05 -4.5,1 r0 bottom (schematic designator C91)
C160 "0.47uF" CAPC0603X33X15NL03T05 -4.5,-2 r180 bottom (schematic designator C69)
C161 "100n" CC1005-0402 -6.5,-2.1 r0 bottom (schematic designator C90)
C162 "0.47uF" CAPC0603X33X15NL03T05 -6,-10.5 r90 bottom (schematic designator C136)
C163 "0.47uF" CAPC0603X33X15NL03T05 -6,11.5 r270 bottom (schematic designator C124)
C164 "0.47uF" CAPC0603X33X15NL03T05 -6.5,1 r0 bottom (schematic designator C137)
C165 "10u" CC2013-0805 -8,-14.5 r0 bottom (schematic designator C99)
C166 "100n" CC1005-0402 -8.5,-5.1 r0 bottom (schematic designator C93)
C167 "4.7uF" CC1608-0603 -9.3,13.4 r180 bottom (schematic designator C138)
C168 "4.7uF" CC1608-0603 -9.3,15.4 r180 bottom (schematic designator C139)
C169 "4.7uF" CC1608-0603 -9.3,17.4 r180 bottom (schematic designator C58)
C170 "4.7u" CC2013-0805 -9,-17.5 r270 bottom (schematic designator C101)
C171 "0.47uF" CAPC0603X33X15NL03T05 -9,-11.5 r90 bottom (schematic designator C140)
C172 "0.47uF" CAPC0603X33X15NL03T05 -9.5,10.5 r315 bottom (schematic designator C122)
C173 "100n" CC1005-0402 -10.5,-6.1 r0 bottom (schematic designator C96)
C174 "100n" CC1005-0402 -10.5,-3.9 r0 bottom (schematic designator C98)
C175 "0.47uF" CAPC0603X33X15NL03T05 -10.5,3 r0 bottom (schematic designator C123)
C176 "1u" CC2013-0805 -10.7,45.4 r270 bottom (schematic designator C169)
C177 "0.47uF" CAPC0603X33X15NL03T05 -11.5,6 r0 bottom (schematic designator C121)
C178 "4.7uF" CC1608-0603 -12.8,13.4 r180 bottom (schematic designator C59)
C179 "4.7uF" CC1608-0603 -12.8,15.4 r180 bottom (schematic designator C112)
C180 "4.7uF" CC1608-0603 -12.8,17.4 r180 bottom (schematic designator C126)
C181 "10u" CC2013-0805 -15.5,-0.7 r180 bottom (schematic designator C100)
C182 "100uF" CC3225-1210 -17.5,13.6 r0 bottom (schematic designator C60)
C183 "47uF" CC3225-1210 -17.5,17.2 r0 bottom (schematic designator C32)
C184 "1u" CC2013-0805 -16.5,-5.7 r270 bottom (schematic designator C95)
C185 "220n" CC1005-0402 -18.35,-43.7 r90 bottom (schematic designator C86)
C186 "220n" CC1005-0402 -19.35,-43.7 r90 bottom (schematic designator C84)
C187 "100n" CC1005-0402 -21.5,-36.5 r180 bottom (schematic designator C151)
C188 "100n" CC1005-0402 -21.5,-35.5 r180 bottom (schematic designator C150)
C189 "4.7u" CC2013-0805 -22.5,-0.6 r0 bottom (schematic designator C102)
C190 "10n" CC1005-0402 -21.344,-43.7 r90 bottom (schematic designator C83)
C191 "10n" CC1005-0402 -22.35,-43.7 r90 bottom (schematic designator C82)
C192 "100n" CC2013-0805 -27.5,28.7 r180 bottom (schematic designator C141)
C193 "1u" CC1608-0603 -27.5,0.5 r270 bottom (schematic designator C174)
C194 "1u" CC1608-0603 -32.5,0.5 r270 bottom (schematic designator C171)
C195 "1u" CC2013-0805 -34.9,-35.3 r270 bottom (schematic designator C181)
C196 "10u" CC2013-0805 -35.4,0.3 r270 bottom (schematic designator C182)
C197 "10n" CC2013-0805 -37.4,-32 r0 bottom (schematic designator C178)
C198 "10u" CC2013-0805 -40,-27 r90 bottom (schematic designator C35)
C199 "1u" CC1608-0603 -40,-4.1 r270 bottom (schematic designator C170)
C200 "47u" CC3216-1206 -40.5,-35.3 r270 bottom (schematic designator C179)
C201 "10u" CC2013-0805 -43.2,-38.8 r90 bottom (schematic designator C162)
C202 "1u" CC1608-0603 -45,-10.2 r0 bottom (schematic designator C154)
C203 "1u" CC2013-0805 -46,-29.5 r0 bottom (schematic designator C184)
C204 "1u" CC1608-0603 -49,-10.2 r0 bottom (schematic designator C159)
C205 "47u" CC3216-1206 -51.5,-26 r180 bottom (schematic designator C87)
C206 "1u" CC1608-0603 -53,-10.2 r0 bottom (schematic designator C156)
C207 "100n" CC2013-0805 -54.5,-29.5 r180 bottom (schematic designator C183)
C208 "1u" CC1608-0603 -57,-10.2 r0 bottom (schematic designator C166)
C209 "100n" CC2013-0805 -58.5,-19.7 r180 bottom (schematic designator C172)
C210 "10n" CC2013-0805 -58.5,-29.5 r0 bottom (schematic designator C173)
D1 "LSM115JE3/TR13" MCSM-DO-214BA-2_L 75,-16 r90 top (schematic designator D2)
D2 "LSM115JE3/TR13" MCSM-DO-214BA-2_L -7,-32.5 r0 bottom (schematic designator D1)
DS1 "LED" LED-0805 -33,-10.5 r90 top (schematic designator DS2)
DS2 "APJA2107EC" KING-LED2107-13-RED-2_V 95,39.6 r90 bottom (schematic designator DS7)
DS3 "APJA2107EC" KING-LED2107-13-RED-2_V 95,46.5 r90 bottom (schematic designator DS1)
FL1 "BNX016-01" MURA-BNX016-01_V -11,-38.5 r0 top locked (schematic designator FL5)
FL2 "BNX016-01" MURA-BNX016-01_V 1,-38.5 r0 top locked
FL3 "BNX016-01" MURA-BNX016-01_V 13,-38.5 r180 top
FL4 "BNX016-01" MURA-BNX016-01_V 77,-24.5 r90 top (schematic designator FL1)
FL5 "BNX016-01" MURA-BNX016-01_V 77,0 r90 top locked (schematic designator FL4)
FR1 "BLM31PG121" CC3216-1206 -30,4.5 r180 top (schematic designator FR3)
FR2 "BLM31PG121" CC3216-1206 -21.5,2.2 r0 top
FR3 "BLM31PG121" CC3216-1206 52,-9 r0 bottom (schematic designator FR1)
FR4 "BLM31PG121" CC3216-1206 -28.2,-4.1 r180 bottom (schematic designator FR5)
FR5 "BLM31PG121" CC3216-1206 -34,3.5 r0 bottom (schematic designator FR4)
FR6 "BLM31PG121" CC3216-1206 -55.3,-7.5 r180 bottom
J1 "AFBR-5710" MSA/SFP2x10 57.7,39.67 r180 top locked
J2 "45558-0003" 455580003 82.106,-33.969 r270 top (schematic designator J6)
J3 "DB25F" DB25F-RA 87,-3 r270 top locked
J4 "SMA" SMA-RA 91.5,28.5 r90 top (schematic designator J2)
L1 "100nH" CL2520-1008 -17.1,-9 r0 top (schematic designator L8)
L2 "XFL4020-222" FP-XAL40-MFG 44.922,-36.686 r270 top value=10uH (schematic designator L10)
L3 "XFL4020-472" FP-XAL40-MFG 44.922,-24.875 r90 top value=10uH (schematic designator L7)
L4 "XFL4020-332" FP-XAL40-MFG 63.591,-36.686 r0 top value=10uH (schematic designator L6)
L5 "XFL4020-222" FP-XAL40-MFG 63.591,-24.875 r0 top value=10uH (schematic designator L4)
L6 "1uH" CL2520-1008 50,39.2 r270 bottom (schematic designator L2)
L7 "1uH" CL2520-1008 50,46.5 r90 bottom (schematic designator L1)
L8 "100nH" CL2520-1008 5,-17.5 r0 bottom (schematic designator L3)
LOGO1 "LIGO logo" LIGO-LOGO-SM -77.25,48.25 r0 top
P1 "182-037-113R531" NORCO-182-037-113R531_V -73.375,-6.625 r270 top locked (schematic designator P199)
P2 "09 18 108 9621" 9181089621 -58,25.5 r90 top (schematic designator P77)
P3 "2mm Header 2x7" 2MM_HDR2X7_RA -37,43.5 r0 top
P4 "PCIeX1-GF-2D-1000-1K-O36" PCIeX1-GF-2D-1000-1K-O36 -26.85,-55.5 r0 top (schematic designator P1)
P5 "QSE40" QSE040 8.02,-25.74 r0 top locked (schematic designator P222)
P6 "QSE40" QSE040 8.02,45.38 r0 top locked (schematic designator P223)
Q1 "FDV301N" SO-G3/C2.25 -30,-11 r180 top (schematic designator Q3)
Q2 "MMBT3906LT1G" ONSC-SOT-23-3-318-08_V 28.5,-6 r90 top (schematic designator Q5)
Q3 "MMBT3906LT1G" ONSC-SOT-23-3-318-08_V 33,-6 r90 top (schematic designator Q6)
Q4 "SI7252DP-T1-GE3" VISH-POWERPAKSO-8_A_V 62,-30.75 r180 top (schematic designator Q2)
Q5 "FDV301N" SO-G3/C2.25 92,49 r90 bottom (schematic designator Q1)
Q6 "FDV301N" SO-G3/C2.25 25,-38.5 r0 bottom (schematic designator Q4)
R1 "20" CR2012-0805 -63,-40.5 r180 top (schematic designator R67)
R2 "20" CR2012-0805 -63,-38.5 r180 top (schematic designator R65)
R3 "4.99K" CR2012-0805 -60.5,-26 r180 top (schematic designator R71)
R4 "10K" CR2012-0805 -58,-30 r270 top (schematic designator R69)
R5 "220" CR1608-0603 -57,-7.5 r0 top (schematic designator R190)
R6 "220" CR1608-0603 -53,-7.5 r0 top (schematic designator R170)
R7 "4.99K" CR2012-0805 -52.5,-26 r180 top (schematic designator R73)
R8 "10K" CR2012-0805 -52.5,-43 r180 top (schematic designator R105)
R9 "10K" CR2012-0805 -52.5,-36 r180 top (schematic designator R107)
R10 "220" CR1608-0603 -49,-7.5 r180 top (schematic designator R182)
R11 "10K" CR2012-0805 -47.1,-32 r270 top (schematic designator R68)
R12 "220" CR1608-0603 -45,-7.5 r180 top (schematic designator R156)
R13 "10K" CR2012-0805 -44.1,-32 r180 top (schematic designator R70)
R14 "100K" CR2012-0805 -44.1,-30 r180 top (schematic designator R74)
R15 "4.99K" CR2012-0805 -44.6,-39.5 r90 top (schematic designator R110)
R16 "6.42K" CR1608-0603 -41.5,-7.5 r90 top (schematic designator R200)
R17 "DNP" CR1608-0603 -40,-1.7 r180 top (schematic designator R199)
R18 "100" CR1608-0603 -38.5,-7.5 r270 top (schematic designator R201)
R19 "DNP" CR1608-0603 -36,-4.1 r270 top (schematic designator R203)
R20 "100" CR1005-0402 -34,39.5 r270 top (schematic designator R60)
R21 "1K" CR1005-0402 -33,-8 r180 top (schematic designator R28)
R22 "100" CR1005-0402 -32,39.5 r270 top (schematic designator R59)
R23 "49.9" CR1608-0603 -30,-6.5 r0 top (schematic designator R165)
R24 "49.9" CR1608-0603 -30,-3.4 r0 top (schematic designator R169)
R25 "4.7k" CR1005-0402 -30,-8 r180 top (schematic designator R52)
R26 "100" CR1005-0402 -30,39.5 r270 top (schematic designator R58)
R27 "100" CR1005-0402 -28,39.5 r270 top (schematic designator R56)
R28 "NS" CR1005-0402 5,13 r90 top (schematic designator R32)
R29 "1K" CR1005-0402 6,13 r90 top (schematic designator R111)
R30 "100" CR1005-0402 17,26.973 r270 top (schematic designator R62)
R31 "100" CR1005-0402 19.012,26.995 r270 top (schematic designator R61)
R32 "1.8k" CR1005-0402 20.65,24.825 r180 top (schematic designator R1)
R33 "1.8k" CR1005-0402 20.65,32.445 r180 top (schematic designator R54)
R34 "NL" CR1005-0402 20.65,23.555 r0 top (schematic designator R29)
R35 "100" CR1005-0402 21,27 r90 top (schematic designator R33)
R36 "NL" CR1005-0402 26.1,22 r180 top (schematic designator R30)
R37 "1.00K" CR1005-0402 26.3,-43 r0 top (schematic designator R115)
R38 "4.7k" CR1005-0402 26.493,17 r90 top (schematic designator R195)
R39 "100" CR1005-0402 28,21.5 r270 top (schematic designator R63)
R40 "1.8k" CR1005-0402 29.905,22 r0 top (schematic designator R55)
R41 "10" CR2012-0805 33,0.5 r0 top (schematic designator R10)
R42 "4.7k" CR1005-0402 35.42,31.175 r180 top (schematic designator R50)
R43 "1.8k" CR1005-0402 35.42,26.095 r0 top (schematic designator R66)
R44 "1.8k" CR1005-0402 35.42,32.445 r0 top (schematic designator R53)
R45 "10K" CR2012-0805 37.5,-6 r90 top (schematic designator R198)
R46 "100" CR2012-0805 39,-11.5 r0 top (schematic designator R112)
R47 "100" CR2012-0805 39,-9.5 r0 top (schematic designator R197)
R48 "10m" CR3225-1210 40.9,-21.6 r270 top (schematic designator R130)
R49 "10m" CR3225-1210 41.187,-40.187 r270 top (schematic designator R133)
R50 "10K" CR2012-0805 43.5,7 r0 top (schematic designator R25)
R51 "10K" CR2012-0805 43.5,15 r0 top (schematic designator R16)
R52 "1.91k" CR1005-0402 43.5,-32.079 r0 top (schematic designator R137)
R53 "392" CR2012-0805 44,41.5 r180 top (schematic designator R14)
R54 "392" CR2012-0805 44,39.5 r0 top (schematic designator R13)
R55 "49.9" CR2012-0805 44,44 r0 top (schematic designator R9)
R56 "49.9" CR2012-0805 44,46 r0 top (schematic designator R12)
R57 "22K" CR2012-0805 44,48 r0 top (schematic designator R11)
R58 "4.99k" CR1005-0402 42.85,-29.562 r90 top (schematic designator R136)
R59 "10K" CR2012-0805 47.5,7 r0 top (schematic designator R26)
R60 "10K" CR2012-0805 47.5,15 r0 top (schematic designator R17)
R61 "NS" CR1005-0402 49.8,-43 r180 top (schematic designator R4)
R62 "2k" CR1005-0402 49.8,-41.9 r0 top (schematic designator R57)
R63 "0" CR1005-0402 49.8,-40.8 r0 top (schematic designator R41)
R64 "30K" CR2012-0805 51.5,15 r0 top (schematic designator R15)
R65 "15k" CR1005-0402 50.4,-36 r90 top (schematic designator R147)
R66 "9.31k" CR1005-0402 51.3,-25 r270 top (schematic designator R145)
R67 "31.6k" CR1005-0402 52.2,-37.8 r180 top (schematic designator R134)
R68 "12.7k" CR1005-0402 52.2,-22 r180 top (schematic designator R131)
R69 "10.2k" CR1005-0402 52.2,-36.5 r0 top (schematic designator R135)
R70 "10.2k" CR1005-0402 52.2,-23 r0 top (schematic designator R132)
R71 "NS" CR1005-0402 52,-40.2 r90 top (schematic designator R42)
R72 "2k" CR1005-0402 53.5,-43 r0 top (schematic designator R31)
R73 "0" CR1005-0402 53,-40.2 r270 top (schematic designator R5)
R74 "NS" CR1005-0402 54,-40.2 r90 top (schematic designator R44)
R75 "40k" CR1005-0402 54.8,-36.5 r180 top (schematic designator R125)
R76 "10.2k" CR1005-0402 54.8,-23 r180 top (schematic designator R37)
R77 "10k" CR1005-0402 54.8,-37.8 r0 top (schematic designator R124)
R78 "21.6k" CR1005-0402 54.8,-22 r0 top (schematic designator R38)
R79 "30K" CR2012-0805 55.5,7.5 r0 top (schematic designator R27)
R80 "37k" CR1005-0402 54.4,-25 r90 top (schematic designator R129)
R81 "NS" CR1005-0402 55,-40.2 r90 top (schematic designator R46)
R82 "56.2k" CR1005-0402 55.7,-25 r270 top (schematic designator R126)
R83 "2k" CR1005-0402 57.3,-43 r180 top (schematic designator R82)
R84 "0" CR1005-0402 57.3,-41.9 r180 top (schematic designator R43)
R85 "0" CR1005-0402 57.3,-40.8 r180 top (schematic designator R45)
R86 "7.15k" CR1005-0402 56.6,-36.05 r90 top (schematic designator R141)
R87 "1.00K" CR2012-0805 62,12.1 r180 top (schematic designator R19)
R88 "7.15K" CR2012-0805 62,6.2 r0 top (schematic designator R22)
R89 "10k" CR2012-0805 62,8.2 r0 top (schematic designator R18)
R90 "10K" CR2012-0805 62,14 r0 top (schematic designator R23)
R91 "10K" CR2012-0805 62,16 r0 top (schematic designator R24)
R92 "1.00K" CR2012-0805 63,-6.5 r90 top (schematic designator R21)
R93 "47k" CR1005-0402 66.25,-32 r270 top (schematic designator R122)
R94 "NL (47k)" CR1005-0402 66.25,-29.5 r270 top (schematic designator R121)
R95 "1.00K" CR2012-0805 67,-6.5 r90 top (schematic designator R20)
R96 "10m" CR3225-1210 68.375,-40.187 r270 top (schematic designator R123)
R97 "10m" CR3225-1210 68.375,-21.437 r90 top (schematic designator R120)
R98 "22K" CR2012-0805 71,31 r180 top (schematic designator R81)
R99 "10m" CR3225-1210 73.7,-9.2 r90 top (schematic designator R196)
R100 "49.9" CR3216-1206 75.5,28.5 r270 top (schematic designator R76)
R101 "261" CR3216-1206 83.5,28.5 r270 top (schematic designator R78)
R102 "20" CR3216-1206 86,28.5 r90 top (schematic designator R47)
R103 "100" CR2012-0805 92,37.5 r180 bottom (schematic designator R3)
R104 "100" CR2012-0805 92,44.5 r180 bottom (schematic designator R2)
R105 "261" CR2012-0805 88,28.5 r0 bottom (schematic designator R77)
R106 "NL" CR2012-0805 85.5,31 r180 bottom (schematic designator R79)
R107 "10" CR2012-0805 81.5,42.5 r180 bottom (schematic designator R8)
R108 "10" CR1005-0402 60.25,-27.062 r0 bottom (schematic designator R39)
R109 "4.65k" CR1005-0402 59,-25 r90 bottom (schematic designator R138)
R110 "Resistor Array" RES4-0.8 58.45,42.87 r180 bottom value=4.7K (schematic designator R7)
R111 "4.7k" CR1005-0402 57.5,40.47 r180 bottom (schematic designator R6)
R112 "4.7k" CR1005-0402 57.5,44.47 r180 bottom (schematic designator R151)
R113 "4.7k" CR1005-0402 57.5,46.07 r180 bottom (schematic designator R152)
R114 "7.15k" CR1005-0402 57.9,-25 r270 bottom (schematic designator R139)
R115 "0" CR1005-0402 56.8,-25 r270 bottom (schematic designator R142)
R116 "2k" CR1005-0402 56.5,-41.35 r90 bottom (schematic designator R83)
R117 "NL" CR1005-0402 55.7,-25 r90 bottom (schematic designator R140)
R118 "0" CR1005-0402 54.4,-25 r270 bottom (schematic designator R40)
R119 "NL (0)" CR1005-0402 53.5,-25 r90 bottom (schematic designator R128)
R120 "100k" CR1005-0402 52.5,-25 r270 bottom (schematic designator R127)
R121 "402k" CR1005-0402 51.3,-25 r90 bottom (schematic designator R146)
R122 "10k" CR1005-0402 50,-35.25 r0 bottom (schematic designator R150)
R123 "9.53k" CR1005-0402 50,-33.75 r180 bottom (schematic designator R149)
R124 "301k" CR1005-0402 50.3,-25 r270 bottom (schematic designator R148)
R125 "7.15k" CR1005-0402 49.3,-25 r90 bottom (schematic designator R143)
R126 "7.15k" CR1005-0402 48,-25.05 r90 bottom (schematic designator R144)
R127 "7.15K" CR2012-0805 35.2,1.8 r270 bottom (schematic designator R48)
R128 "1.00K" CR2012-0805 35.2,5.3 r90 bottom (schematic designator R49)
R129 "100K" CR1608-0603 34.1,-0.4 r180 bottom (schematic designator R171)
R130 "4.7k" CR1005-0402 15,-5.5 r0 bottom (schematic designator R64)
R131 "4.7k" CR1005-0402 15,-4.5 r0 bottom (schematic designator R116)
R132 "4.7k" CR1005-0402 15,-3.5 r0 bottom (schematic designator R114)
R133 "4.7k" CR1005-0402 15,-2.5 r0 bottom (schematic designator R113)
R134 "4.7k" CR1005-0402 15,-1.5 r0 bottom (schematic designator R51)
R135 "49.9K" CR1005-0402 2,-17.5 r90 bottom (schematic designator R84)
R136 "100" CR2012-0805 -1,-32.5 r90 bottom (schematic designator R193)
R137 "300" CR1005-0402 -1.5,-20 r0 bottom (schematic designator R90)
R138 "49.9K" CR1005-0402 -3,-21 r180 bottom (schematic designator R88)
R139 "100" CR2012-0805 -3,-32.5 r90 bottom (schematic designator R191)
R140 "100K" CR1005-0402 -4.5,-20 r180 bottom (schematic designator R86)
R141 "100K" CR1608-0603 -5,-41 r180 bottom (schematic designator R167)
R142 "10m" CR3225-1210 -5,-37 r270 bottom (schematic designator R34)
R143 "10K" CR1005-0402 -7.5,-17.5 r270 bottom (schematic designator R91)
R144 "100" CR1608-0603 -15.6,-2.5 r180 bottom (schematic designator R80)
R145 "15" CR1005-0402 -17,-43.7 r90 bottom (schematic designator R117)
R146 "NL" CR1005-0402 -17.2,-36 r270 bottom (schematic designator R118)
R147 "NL" CR1005-0402 -19,-38.5 r180 bottom (schematic designator R119)
R148 "49.9K" CR1005-0402 -19.5,-9.5 r0 bottom (schematic designator R85)
R149 "12.1K" CR1005-0402 -19.5,-0.3 r180 bottom (schematic designator R93)
R150 "300" CR1005-0402 -22,-6 r270 bottom (schematic designator R92)
R151 "49.9K" CR1005-0402 -22,-2.7 r90 bottom (schematic designator R89)
R152 "133K" CR1005-0402 -23,-2.7 r270 bottom (schematic designator R87)
R153 "0" CR1005-0402 -24.813,-43.687 r180 bottom (schematic designator R36)
R154 "100" CR2012-0805 -38,23 r270 bottom (schematic designator R104)
R155 "100" CR2012-0805 -38,28 r90 bottom (schematic designator R106)
R156 "4.7k" CR1005-0402 -40,45.5 r0 bottom (schematic designator R35)
R157 "100" CR2012-0805 -40,23 r270 bottom (schematic designator R103)
R158 "100" CR2012-0805 -40,28 r90 bottom (schematic designator R108)
R159 "100K" CR1608-0603 -42,-19.5 r180 bottom (schematic designator R183)
R160 "100" CR2012-0805 -42,23 r270 bottom (schematic designator R102)
R161 "100" CR2012-0805 -42,28 r90 bottom (schematic designator R109)
R162 "7.15K" CR1608-0603 -43.5,0.5 r90 bottom (schematic designator R168)
R163 "100" CR1608-0603 -43.6,-13.4 r270 bottom (schematic designator R162)
R164 "100" CR2012-0805 -45,23 r270 bottom (schematic designator R98)
R165 "100" CR2012-0805 -45,28 r90 bottom (schematic designator R99)
R166 "10K" CR1608-0603 -45,0.5 r90 bottom (schematic designator R172)
R167 "6.42K" CR1608-0603 -45,-13.4 r270 bottom (schematic designator R159)
R168 "40.2K" CR1608-0603 -46,-19.5 r180 bottom (schematic designator R154)
R169 "3.01K" CR1608-0603 -46.3,-13.4 r270 bottom (schematic designator R153)
R170 "10K" CR1608-0603 -46.5,-3.5 r90 bottom (schematic designator R180)
R171 "10K" CR1608-0603 -46.5,0.5 r90 bottom (schematic designator R181)
R172 "100" CR2012-0805 -47,23 r270 bottom (schematic designator R97)
R173 "100" CR2012-0805 -47,28 r90 bottom (schematic designator R100)
R174 "100" CR1608-0603 -47.6,-13.4 r270 bottom (schematic designator R188)
R175 "4.99K" CR1608-0603 -48,-3.5 r90 bottom (schematic designator R163)
R176 "10K" CR1608-0603 -48,0.5 r90 bottom (schematic designator R164)
R177 "100" CR2012-0805 -49,23 r270 bottom (schematic designator R96)
R178 "100" CR2012-0805 -49,28 r90 bottom (schematic designator R101)
R179 "6.42K" CR1608-0603 -49,-13.4 r270 bottom (schematic designator R185)
R180 "49.9K" CR1608-0603 -50,-19.5 r180 bottom (schematic designator R186)
R181 "4.99K" CR1608-0603 -49.5,-3.5 r90 bottom (schematic designator R160)
R182 "10K" CR1608-0603 -49.5,0.5 r90 bottom (schematic designator R161)
R183 "20" CR1005-0402 -50.5,-29.9 r0 bottom (schematic designator R72)
R184 "10K" CR1005-0402 -50.5,-28.8 r0 bottom (schematic designator R75)
R185 "1K" CR1608-0603 -50.3,-13.4 r270 bottom (schematic designator R179)
R186 "30.1K" CR1608-0603 -51,-3.5 r90 bottom (schematic designator R157)
R187 "10K" CR1608-0603 -51,0.5 r90 bottom (schematic designator R158)
R188 "100" CR1608-0603 -51.6,-13.4 r270 bottom (schematic designator R176)
R189 "49.9K" CR1608-0603 -52.5,-3.5 r90 bottom (schematic designator R177)
R190 "10K" CR1608-0603 -52.5,0.5 r90 bottom (schematic designator R178)
R191 "6.42K" CR1608-0603 -53,-13.4 r270 bottom (schematic designator R173)
R192 "49.9K" CR1608-0603 -54,-19.5 r180 bottom (schematic designator R174)
R193 "7.15K" CR1608-0603 -54,0.5 r90 bottom (schematic designator R184)
R194 "1K" CR1608-0603 -54.3,-13.4 r270 bottom (schematic designator R166)
R195 "10K" CR1608-0603 -55.5,0.5 r90 bottom (schematic designator R155)
R196 "100" CR1608-0603 -55.6,-13.4 r270 bottom (schematic designator R194)
R197 "6.42K" CR1608-0603 -57,-13.4 r270 bottom (schematic designator R192)
R198 "10K" CR1608-0603 -57,0.5 r90 bottom (schematic designator R187)
R199 "1K" CR1608-0603 -58.3,-13.4 r270 bottom (schematic designator R189)
R200 "10K" CR1608-0603 -58.5,0.5 r90 bottom (schematic designator R175)
R201 "NL" CR1005-0402 -66.9,-24.6 r225 bottom (schematic designator R94)
R202 "NL" CR1005-0402 -67.6,-23.9 r225 bottom (schematic designator R95)
S1 "SW DIP-8" DIP_SW_8WAY_SMD_SIDE -52.6,45.3 r180 top locked (schematic designator S2)
S2 "B3SN-3112P" SW_SMD_6MM -44,45.5 r180 bottom (schematic designator S1)
T1 "1:1" AT224-3 78,29.77 r0 top
TP1 "Testpoint" TP1-RED#1 -53.5,-21.5 r90 top (schematic designator TP13)
TP2 "Testpoint" TP1-WHT -49.5,-21.5 r270 top (schematic designator TP14)
TP3 "Testpoint" TP1-RED#1 -42.5,-42.4 r270 top (schematic designator TP25)
TP4 "Testpoint" TP1-BLK#1 -37,39.5 r270 top (schematic designator TP24)
TP5 "Testpoint" TP1-WHT -29,-42.5 r270 top (schematic designator TP26)
TP6 "Testpoint" TP1-BLK#1 -29,-38.5 r270 top (schematic designator TP11)
TP7 "Testpoint" TP1-RED#1 -29,-34.5 r90 top (schematic designator TP15)
TP8 "Testpoint" TP1-BLK#1 33,36.5 r270 top (schematic designator TP23)
TP9 "Testpoint" TP1-RED#1 41,-30.75 r90 top (schematic designator TP19)
TP10 "Testpoint" TP1-RED#1 41,-25.5 r90 top (schematic designator TP17)
TP11 "Testpoint" TP1-YLW#1 44,-19.7 r0 top (schematic designator TP8)
TP12 "Testpoint" TP1-RED#1 45,-42.25 r90 top (schematic designator TP18)
TP13 "Testpoint" TP1-BLK#1 48.5,-19.75 r90 top (schematic designator TP22)
TP14 "Testpoint" TP1-BLK#1 51,-17.5 r90 top (schematic designator TP21)
TP15 "Testpoint" TP1-RED#1 53.5,-19.75 r90 top (schematic designator TP3)
TP16 "Testpoint" TP1-YLW#2 55.5,17 r180 top (schematic designator TP2)
TP17 "Testpoint" TP1-YLW#2 55.5,21 r180 top (schematic designator TP1)
TP18 "Testpoint" TP1-BLK#1 56,-17.5 r90 top (schematic designator TP10)
TP19 "Testpoint" TP1-RED#1 58.5,-19.75 r90 top (schematic designator TP5)
TP20 "Testpoint" TP1-BLK#2 61,-42.562 r90 top
TP21 "Testpoint" TP1-RED#1 63.5,-19.75 r0 top (schematic designator TP4)
TP22 "Testpoint" TP1-RED#2 65,-42.55 r90 top (schematic designator TP16)
TP23 "Testpoint" TP1-BLK#1 71,22.5 r270 top (schematic designator TP9)
TP24 "Testpoint" TP1-BLK#1 74.2,-40.734 r0 top (schematic designator TP7)
TP25 "Testpoint" TP1-RED#1 74.2,-35.734 r0 top (schematic designator TP6)
TP26 "Testpoint" TP1-YLW#2 79.5,24.5 r90 top (schematic designator TP12)
U1 "INA333AIDGKR" DGK0008A_N -57,-12.5 r90 top (schematic designator U35)
U2 "ADG706BRU" ADI-RU-28_M -51,-1 r270 top locked (schematic designator U27)
U3 "OP184ES" SO-8_N -52.5,-39.5 r180 top (schematic designator U44)
U4 "OP284ES" SO-8_N -52.5,-30 r180 top locked (schematic designator U2)
U5 "INA333AIDGKR" DGK0008A_N -53,-12.5 r90 top (schematic designator U28)
U6 "INA333AIDGKR" DGK0008A_N -49,-12.5 r90 top (schematic designator U32)
U7 "74LVC04" TSSOP14 -47,25.5 r0 top locked (schematic designator U21)
U8 "INA333AIDGKR" DGK0008A_N -45,-12.5 r90 top (schematic designator U26)
U9 "INA333AIDGKR" DGK0008A_N -40,-4.1 r0 top (schematic designator U36)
